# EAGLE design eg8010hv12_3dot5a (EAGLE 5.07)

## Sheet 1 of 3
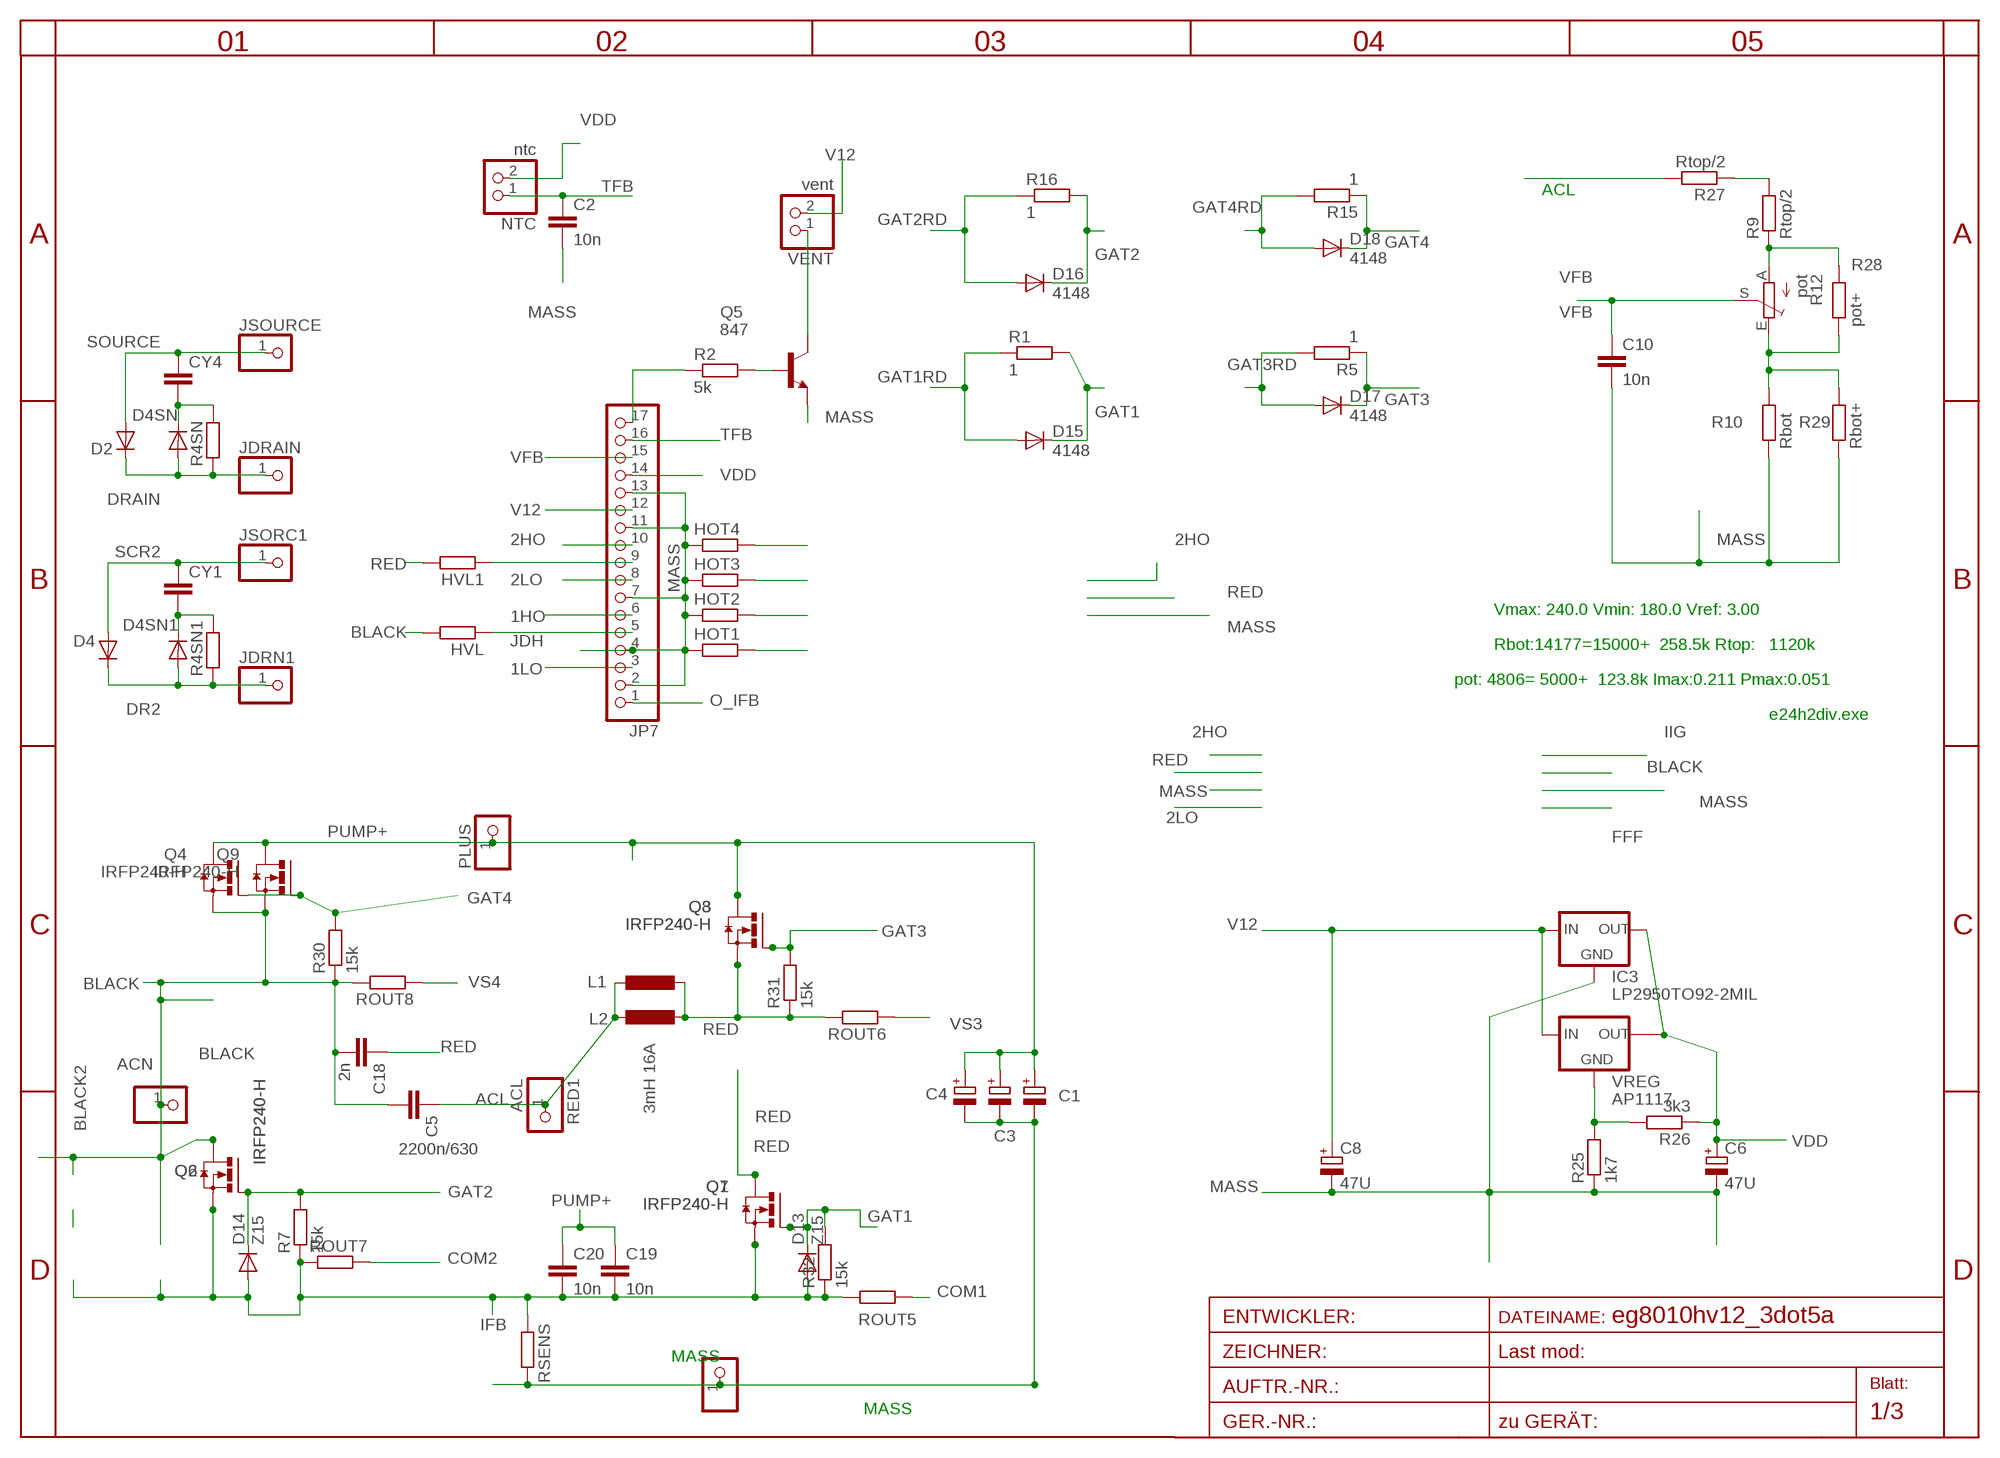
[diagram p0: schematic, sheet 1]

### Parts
BLACK2  ACN  PINHD-1X12MM3  [1X2MM3]
C1  CPOL-EUE5-13  [E5-13]
C2  10n  C-EUC0805  [C0805]
C3  CPOL-EUE5-13  [E5-13]
C4  CPOL-EUE5-13  [E5-13]
C5  2200n/630  C-EU275-173X316  [C275-173X316]
C6  47U  CPOL-EUSMCA  [SMC_A]
C8  47U  CPOL-EUSMCA  [SMC_A]
C10  10n  C-EUC0805  [C0805]
C18  2n  C-EU050-024X044  [C050-024X044]
C19  10n  C-EU050-024X044  [C050-024X044]
C20  10n  C-EU050-024X044  [C050-024X044]
CY1  CXXC10B5  [XC10B5]
CY4  CXXC10B5  [XC10B5]
D2  DIODE-SMC  [SMC]
D4  DIODE-SMC  [SMC]
D4SN  DIODE-P1-10  [P1-10]
D4SN1  DIODE-P1-10  [P1-10]
D13  Z15  DIODE-MINIMELF  [MINIMELF]
D14  Z15  DIODE-MINIMELF  [MINIMELF]
D15  4148  DIODE-MINIMELF  [MINIMELF]
D16  4148  DIODE-MINIMELF  [MINIMELF]
D17  4148  DIODE-MINIMELF  [MINIMELF]
D18  4148  DIODE-MINIMELF  [MINIMELF]
HOT1  R-EU_R0805  [R0805]
HOT2  R-EU_R0805  [R0805]
HOT3  R-EU_R0805  [R0805]
HOT4  R-EU_R0805  [R0805]
HVL  R-EU_R1005  [R1005]
HVL1  R-EU_R1005  [R1005]
IC3  LP2950TO92-2MIL  [TO92-2MIL]
JDRAIN  PINHD-1X11MM0  [1X1MM0]
JDRN1  PINHD-1X11MM0  [1X1MM0]
JP7  PINHD-1X17  [1X17]
JSORC1  PINHD-1X11MM0  [1X1MM0]
JSOURCE  PINHD-1X11MM0  [1X1MM0]
L1  L-EU4.13  [0204/13]
L2  3mH 16A  L-EURNG  [RING]
MINUS  PINHD-1X12MM3  [1X2MM3]
NTC  ntc  PINHD-1X2STR  [1X02]
PLUS  PINHD-1X12MM3  [1X2MM3]
Q1  IRFP240-H  [TO247BH]
Q2  IRFP240-H  [TO247BH]
Q3  IRFP240-H  [TO247BH]
Q4  IRFP240-H  [TO247BH]
Q5  847  BC847SMD  [SOT23]
Q6  IRFP240-H  [TO247BH]
Q7  IRFP240-H  [TO247BH]
Q8  IRFP240-H  [TO247BH]
Q9  IRFP240-H  [TO247BH]
R1  1  R-EU_R2512  [R2512]
R2  5k  R-EU_R0805  [R0805]
R4SN  R-EU_0207/10  [0207/10]
R4SN1  R-EU_0207/10  [0207/10]
R5  1  R-EU_R2512  [R2512]
R7  15k  R-EU_R1206  [R1206]
R9  Rtop/2  R-EU_R1206  [R1206]
R10  Rbot  R-EU_R0805  [R0805]
R12  pot  TRIM_EU-B64Y  [B64Y]
R15  1  R-EU_R2512  [R2512]
R16  1  R-EU_R2512  [R2512]
R25  1k7  R-EU_R0805  [R0805]
R26  3k3  R-EU_R0805  [R0805]
R27  Rtop/2  R-EU_R1206  [R1206]
R28  pot+  R-EU_R0805  [R0805]
R29  Rbot+  R-EU_R0805  [R0805]
R30  15k  R-EU_R1206  [R1206]
R31  15k  R-EU_R1206  [R1206]
R32  15k  R-EU_R1206  [R1206]
RED1  ACL  PINHD-1X12MM3  [1X2MM3]
ROUT5  R-EU_R2512  [R2512]
ROUT6  R-EU_R2512  [R2512]
ROUT7  R-EU_R2512  [R2512]
ROUT8  R-EU_R2512  [R2512]
RSENS  R-EU_WIRE  [WIRE]
VENT  vent  PINHD-1X2STR  [1X02]
VREG  AP1117  [SOT223]

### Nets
1HO: HOT2.2 JP7.6 ; also sheet 3
1LO: HOT1.2 JP7.3 ; also sheet 3
2HO: HOT4.2 JP7.10 ; also sheet 3
2LO: HOT3.2 JP7.8 ; also sheet 3
ACL: C5.1 L1.1 L2.2 R27.2 RED1.1
BLACK: BLACK2.1 C5.2 C18.2 HVL.2 Q2.D Q4.S Q6.D Q9.S R30.1 ROUT8.2
COM1: ROUT5.1 ; also sheet 3
COM2: ROUT7.2 ; also sheet 3
DFG: HVL1.1 JP7.9
DR2: D4.C D4SN1.A JDRN1.1 R4SN1.1
DRAIN: D2.C D4SN.A JDRAIN.1 R4SN.1
GAT1: D13.C D15.C Q1.G Q7.G R1.2 R32.2
GAT1RD: D15.A R1.1 ; also sheet 3
GAT2: D14.C D16.C Q2.G Q6.G R7.2 R16.2
GAT2RD: D16.A R16.1 ; also sheet 3
GAT3: D17.C Q3.G Q8.G R5.1 R31.2
GAT3RD: D17.A R5.2 ; also sheet 3
GAT4: D18.C Q4.G Q9.G R15.1 R30.2
GAT4RD: D18.A R15.2 ; also sheet 3
IFB: C19.2 C20.2 D13.A D14.A Q1.S Q2.S Q6.S Q7.S R7.1 R32.1 ROUT5.2 ROUT7.1 RSENS.1 ; also sheet 2,3
JDH: HVL.1 JP7.5
MASS: C1.- C2.2 C3.- C4.- C6.- C8.- C10.2 HOT1.1 HOT2.1 HOT3.1 HOT4.1 IC3.2(GND) JP7.2 JP7.4 JP7.7 JP7.11 JP7.13 MINUS.1 Q5.2(E) R10.1 R25.1 R29.1 RSENS.2 ; also sheet 2,3
N$1: Q5.3(C) VENT.1
N$2: Q5.1(B) R2.2
N$3: JP7.17 R2.1
N$17: R25.2 R26.2 VREG.1(GND)
N$23: R9.2 R27.1
N$29: R10.2 R12.E R28.1 R29.2
N$30: R9.1 R12.A R28.2
O_IFB: JP7.1 ; also sheet 3
PUMP+: C1.+ C3.+ C4.+ C19.1 C20.1 PLUS.1 Q3.D Q4.D Q8.D Q9.D ; also sheet 2
RED: C18.1 HVL1.2 L1.2 L2.1 Q1.D Q3.S Q7.D Q8.S R31.1 ROUT6.2 ; also sheet 2
SCR2: CY1.1 D4.A JSORC1.1
SNUB1: CY1.2 D4SN1.C R4SN1.2
SNUB2: CY4.2 D4SN.C R4SN.2
SOURCE: CY4.1 D2.A JSOURCE.1
TFB: C2.1 JP7.16 NTC.1 ; also sheet 2
V12: C8.+ IC3.3(IN) JP7.12 VENT.2 VREG.3(IN) ; also sheet 2,3
VDD: C6.+ IC3.1(OUT) JP7.14 NTC.2 R26.1 VREG.4(TAB) ; also sheet 2
VFB: C10.1 JP7.15 R12.S ; also sheet 2
VS3: ROUT6.1 ; also sheet 3
VS4: ROUT8.1 ; also sheet 3
Unconnected: VREG.2(OUT)

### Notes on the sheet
- Vmax: 240.0 Vmin: 180.0 Vref: 3.00
- Rbot:14177=15000+  258.5k Rtop:   1120k
- pot: 4806= 5000+  123.8k Imax:0.211 Pmax:0.051
- e24h2div.exe

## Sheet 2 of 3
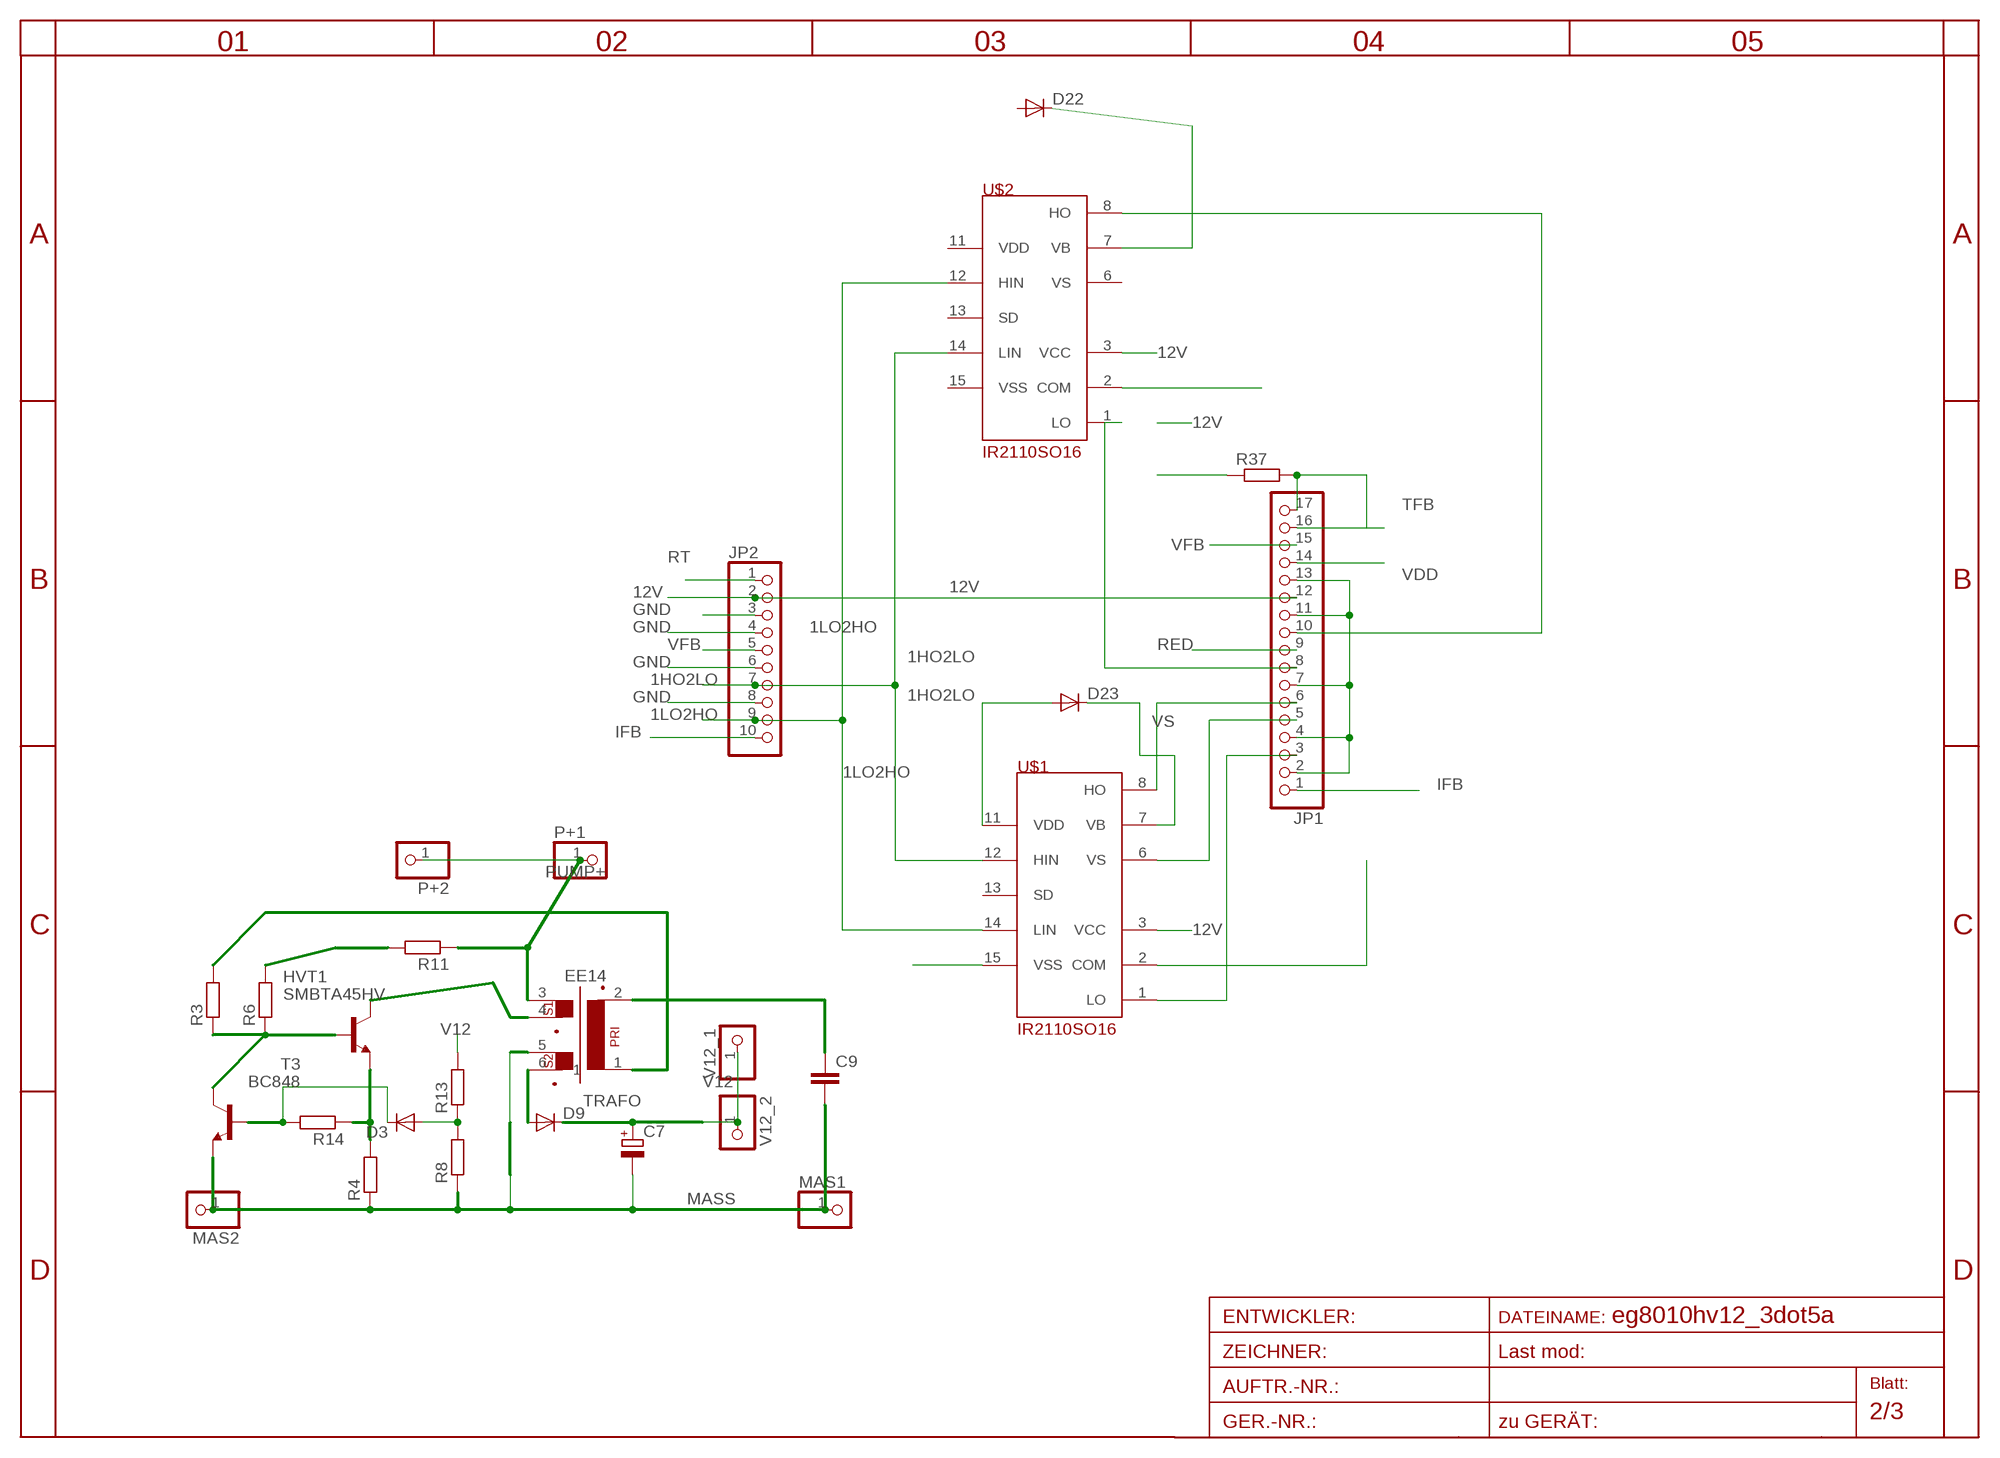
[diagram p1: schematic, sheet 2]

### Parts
C7  CPOL-EUSMCA  [SMC_A]
C9  C-EUC0805  [C0805]
D3  DIODE-MINIMELF  [MINIMELF]
D9  DIODE-SMA-DO214  [SMA-DO214AC]
D22  DIODE-SMA-DO214  [SMA-DO214AC]
D23  DIODE-SMA-DO214  [SMA-DO214AC]
HVT1  SMBTA45HV  [SOT23HV]
JP1  PINHD-1X17  [1X17]
JP2  PINHD-1X100X05  [1X10]
MAS1  PINHD-1X11X0.4  [1X01]
MAS2  PINHD-1X11X0.4  [1X01]
P+1  PINHD-1X11X0.4  [1X01]
P+2  PINHD-1X11X0.4  [1X01]
R3  R-EU_R0805  [R0805]
R4  R-EU_R0805  [R0805]
R6  R-EU_R1206  [R1206]
R8  R-EU_R0805  [R0805]
R11  R-EU_R1206  [R1206]
R13  R-EU_R0805  [R0805]
R14  R-EU_R0805  [R0805]
R37  R-EU_0204/2V  [0204V]
T3  BC848  [SOT23]
TRAFO  EE14  [EE14]
U$1  IR2110SO16  [SO16DW]
U$2  IR2110SO16  [SO16DW]
V12_1  PINHD-1X11X0.4  [1X01]
V12_2  PINHD-1X11X0.4  [1X01]

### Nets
1HO2LO: JP2.7 U$1.12(HIN) U$2.14(LIN)
1LO2HO: JP2.9 U$1.14(LIN) U$2.12(HIN)
12V: D23.A JP1.12 JP2.2 U$1.3(VCC) U$1.11(VDD)
A: D9.A TRAFO.6
B1C2: HVT1.1(B) R3.1 R6.1 T3.C
BT1: D3.C R14.2 T3.B
C1: HVT1.3(C) TRAFO.4
EB: HVT1.2(E) R4.2 R14.1
GND: JP1.2 JP1.4 JP1.7 JP1.11 JP1.13 JP2.3 JP2.4 JP2.6 JP2.8 R37.1
IFB: JP1.1 JP2.10 U$1.2(COM) U$2.2(COM) ; also sheet 1,3
MASS: C7.- C9.2 MAS1.1 MAS2.1 R4.1 R8.1 T3.E TRAFO.5 U$1.15(VSS) ; also sheet 1,3
N$6: R3.2 TRAFO.1
N$7: C9.1 TRAFO.2
N$8: R6.2 R11.2
N$10: D3.A R8.2 R13.1
N$15: JP1.3 U$1.1(LO)
N$19: JP1.6 U$1.8(HO)
N$21: JP1.8 U$2.1(LO)
N$27: JP1.10 U$2.8(HO)
PUMP+: P+1.1 P+2.1 R11.1 TRAFO.3 ; also sheet 1
RED: JP1.9 ; also sheet 1
RT: JP2.1
TFB: JP1.16 JP1.17 R37.2 ; also sheet 1
V12: C7.+ D9.K(C) R13.2 V12_1.1 V12_2.1 ; also sheet 1,3
VB: D22.K(C) D23.K(C) U$1.7(VB) U$2.7(VB)
VDD: JP1.14 ; also sheet 1
VFB: JP1.15 JP2.5 ; also sheet 1
VS: JP1.5 U$1.6(VS)
Unconnected: D22.A U$1.13(SD) U$2.3(VCC) U$2.6(VS) U$2.11(VDD) U$2.13(SD) U$2.15(VSS)

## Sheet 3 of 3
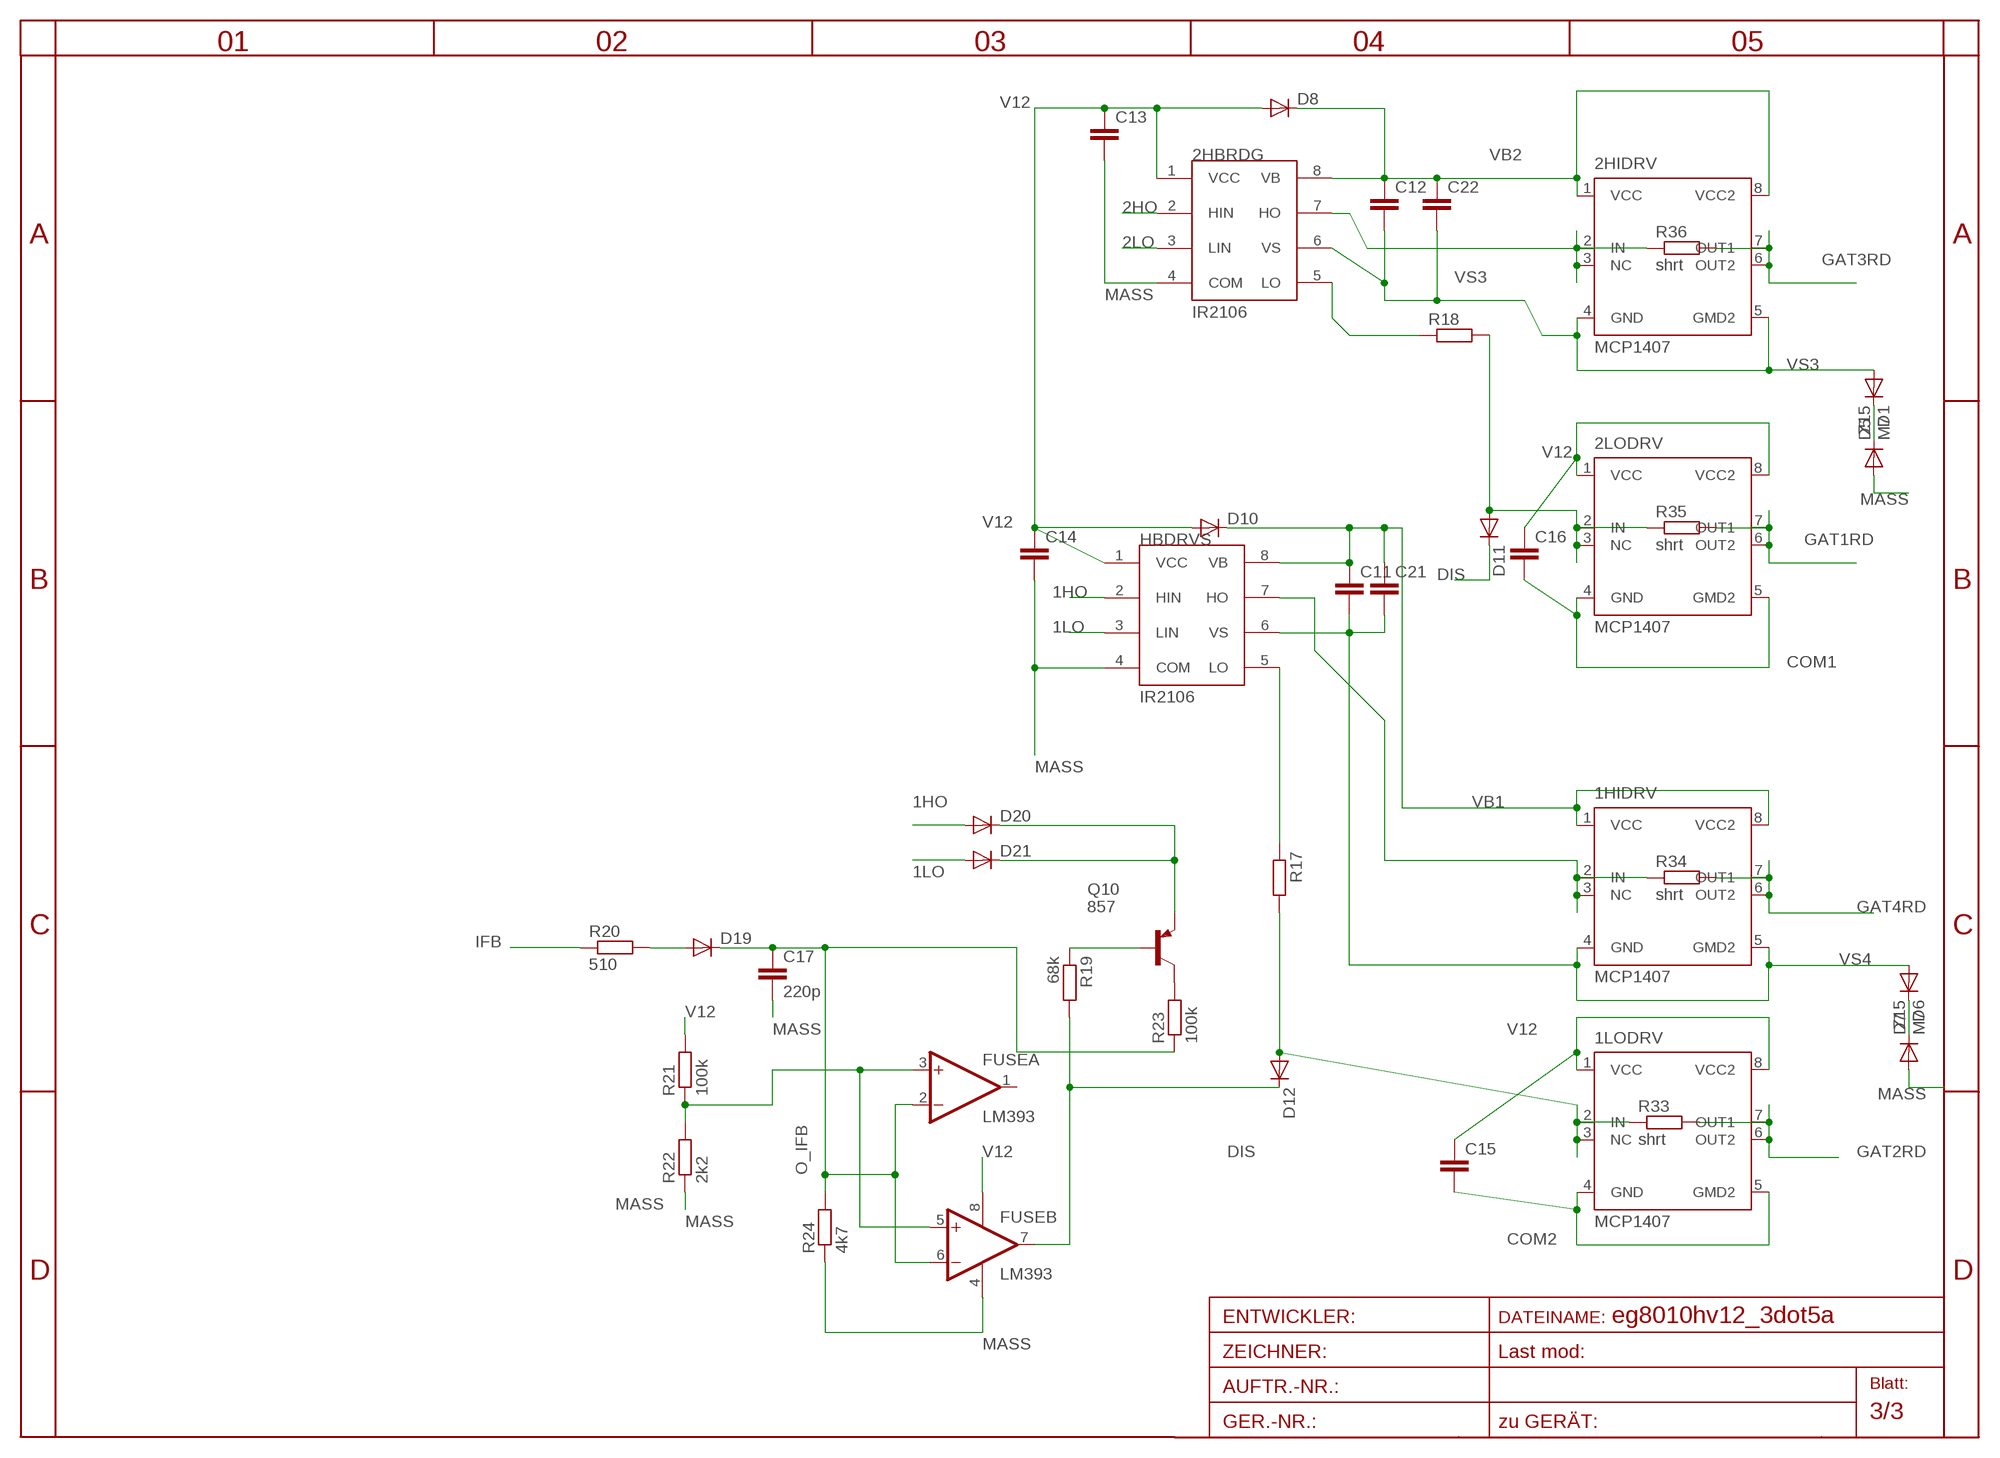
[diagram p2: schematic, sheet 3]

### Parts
1HIDRV  MCP1407  [SO-08M]
1LODRV  MCP1407  [SO-08M]
2HBRDG  IR2106  [SO8-5]
2HIDRV  MCP1407  [SO-08M]
2LODRV  MCP1407  [SO-08M]
C11  C-EUC058MLCC  [C058-020X040]
C12  C-EUC058MLCC  [C058-020X040]
C13  C-EUC1206  [C1206]
C14  C-EUC1206  [C1206]
C15  C-EUC1206  [C1206]
C16  C-EUC1206  [C1206]
C17  220p  C-EUC0805  [C0805]
C21  C-EUC1206  [C1206]
C22  C-EUC1206  [C1206]
D1  Z15  DIODE-MINIMELF  [MINIMELF]
D5  M7  DIODE-SMA-DO214  [SMA-DO214AC]
D6  Z15  DIODE-MINIMELF  [MINIMELF]
D7  M7  DIODE-SMA-DO214  [SMA-DO214AC]
D8  DIODE-SMA-DO214  [SMA-DO214AC]
D10  DIODE-SMA-DO214  [SMA-DO214AC]
D11  DIODE-MINIMELF  [MINIMELF]
D12  DIODE-MINIMELF  [MINIMELF]
D19  DIODE-SOT23  [SOT23]
D20  DIODE-SOT23  [SOT23]
D21  DIODE-SOT23  [SOT23]
FUSE  LM393  LM358D  [SO08]
HBDRVS  IR2106  [SO8-5]
Q10  857  BC857ALT1SMD  [SOT23-BEC]
R17  R-EU_0207-17  [0207/17]
R18  R-EU_0204/5  [0204/5]
R19  68k  R-EU_R0805  [R0805]
R20  510  R-EU_R0805  [R0805]
R21  100k  R-EU_R0805  [R0805]
R22  2k2  R-EU_R0805  [R0805]
R23  100k  R-EU_R0805  [R0805]
R24  4k7  R-EU_R0805  [R0805]
R33  shrt  R-EU_R1206  [R1206]
R34  shrt  R-EU_R1206  [R1206]
R35  shrt  R-EU_R1206  [R1206]
R36  shrt  R-EU_R1206  [R1206]

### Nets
1HO: D20.1(A) HBDRVS.2(HIN) ; also sheet 1
1LO: D21.1(A) HBDRVS.3(LIN) ; also sheet 1
2HO: 2HBRDG.2(HIN) ; also sheet 1
2LO: 2HBRDG.3(LIN) ; also sheet 1
COM1: 2LODRV.4(GND) 2LODRV.5(GMD2) C16.2 ; also sheet 1
COM2: 1LODRV.4(GND) 1LODRV.5(GMD2) C15.2 ; also sheet 1
DIS: D11.C D12.C FUSE.7(B:OUT) R19.2
GAT1RD: 2LODRV.6(OUT2) 2LODRV.7(OUT1) R35.2 ; also sheet 1
GAT2RD: 1LODRV.6(OUT2) 1LODRV.7(OUT1) R33.2 ; also sheet 1
GAT3RD: 2HIDRV.6(OUT2) 2HIDRV.7(OUT1) R36.2 ; also sheet 1
GAT4RD: 1HIDRV.6(OUT2) 1HIDRV.7(OUT1) R34.2 ; also sheet 1
IFB: R20.1 ; also sheet 1,2
MASS: 2HBRDG.4(COM) C13.2 C14.2 C17.2 D5.A D7.A FUSE.4(P:V-) HBDRVS.4(COM) R22.1 R24.1 ; also sheet 1,2
N$4: 2HBRDG.5(LO) R18.1
N$5: 1LODRV.2(IN) 1LODRV.3(NC) D12.A R17.2 R33.1
N$9: FUSE.3(A:+IN) FUSE.5(B:+IN) R21.1 R22.2
N$11: HBDRVS.5(LO) R17.1
N$12: 2HBRDG.7(HO) 2HIDRV.2(IN) 2HIDRV.3(NC) R36.1
N$13: 1HIDRV.2(IN) 1HIDRV.3(NC) HBDRVS.7(HO) R34.1
N$14: D19.1(A) R20.2
N$16: 2LODRV.2(IN) 2LODRV.3(NC) D11.A R18.2 R35.1
N$18: D20.3(C) D21.3(C) Q10.E
N$20: D1.C D5.K(C)
N$24: D6.C D7.K(C)
N$25: Q10.B R19.1
N$26: Q10.C R23.2
O_IFB: C17.1 D19.3(C) FUSE.2(A:-IN) FUSE.6(B:-IN) R23.1 R24.2 ; also sheet 1
V12: 1LODRV.1(VCC) 1LODRV.8(VCC2) 2HBRDG.1(VCC) 2LODRV.1(VCC) 2LODRV.8(VCC2) C13.1 C14.1 C15.1 C16.1 D8.A D10.A FUSE.8(P:V+) HBDRVS.1(VCC) R21.2 ; also sheet 1,2
VB1: 1HIDRV.1(VCC) 1HIDRV.8(VCC2) C11.1 C21.1 D10.K(C) HBDRVS.8(VB)
VB2: 2HBRDG.8(VB) 2HIDRV.1(VCC) 2HIDRV.8(VCC2) C12.1 C22.1 D8.K(C)
VS3: 2HBRDG.6(VS) 2HIDRV.4(GND) 2HIDRV.5(GMD2) C12.2 C22.2 D1.A ; also sheet 1
VS4: 1HIDRV.4(GND) 1HIDRV.5(GMD2) C11.2 C21.2 D6.A HBDRVS.6(VS) ; also sheet 1
Unconnected: FUSE.1(A:OUT)

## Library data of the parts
1HIDRV 1LODRV 2HIDRV 2LODRV = microchip:MCP1407
2HBRDG HBDRVS = irf-2:IR2106
BLACK2 JDRAIN JDRN1 JSORC1 JSOURCE MAS1 MAS2 MINUS P+1 P+2 PLUS RED1 V12_1 V12_2 = pinhead:PINHD-1X1: PIN HEADER
C1 C3 C4 C6-C8 = rcl:CPOL-EU: POLARIZED CAPACITOR, European symbol
C2 C5 C9-C22 = rcl:C-EU: CAPACITOR, European symbol
CY1 CY4 = rcl:CX: X CAPACITOR
D1-D4 D4SN D4SN1 D5-D23 = diode:DIODE-: DIODE
FUSE = linear:LM358: OP AMP also LM158; LM258; LM2904 Source: http://cache.national.com/ds/LM/LM158.pdf
HOT1-HOT4 HVL HVL1 R1-R4 R4SN R4SN1 R5-R8 R11 R13-R24 R30-R37 ROUT5-ROUT8 RSENS = rcl:R-EU_: RESISTOR, European symbol
HVT1 = transistor-npn:SMBTA45
IC3 = v-reg:LP2950?*: Source: http://cache.national.com/ds/LP/LP2950.pdf
JP1 JP7 = pinhead:PINHD-1X17: PIN HEADER
JP2 = pinhead:PINHD-1X10: PIN HEADER
L1 L2 = rcl:L-EU: INDUCTOR, European symbol
NTC VENT = pinhead:PINHD-1X2: PIN HEADER
Q1-Q4 Q6-Q9 = transistor-power:IRFP240: HEXFET Power MosFet Source: http://www.irf.com/
Q5 = transistor-npn:BC847*: NPN Transistor
Q10 = transistor-pnp:BC857*: PNP Transistror
R9 R10 R25-R29 = rcl-2:R-EU_: RESISTOR, European symbol
R12 = pot:TRIM_EU-: POTENTIOMETER
T3 = transistor:BC848: NPN TRANSISTOR
TRAFO = trafo:EE14
U$1 U$2 = ir2112:IR2110
VREG = v-reg:AP1117

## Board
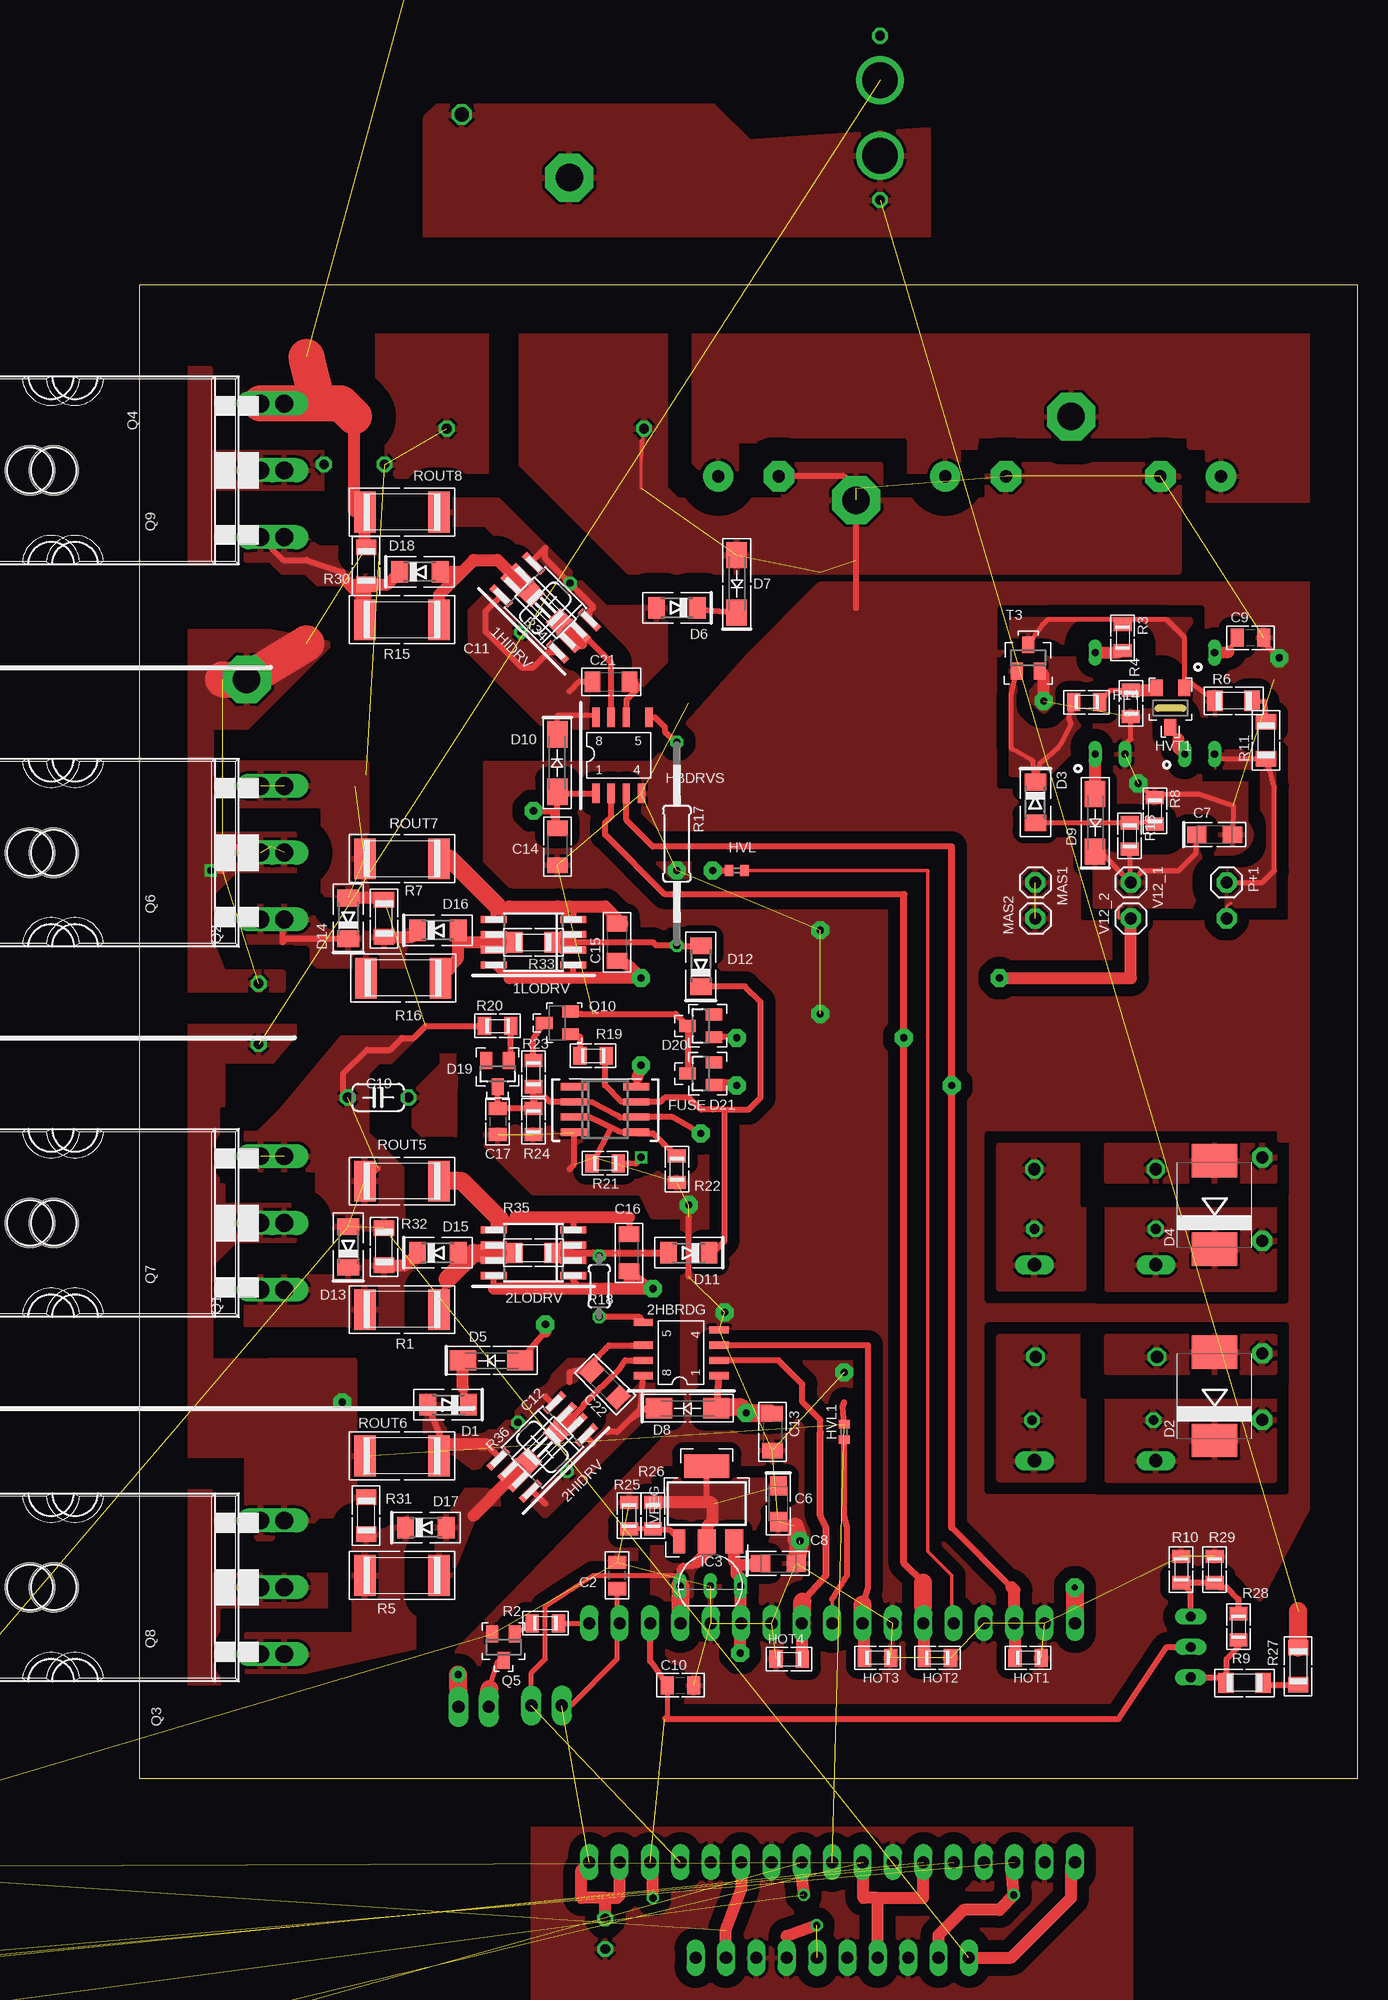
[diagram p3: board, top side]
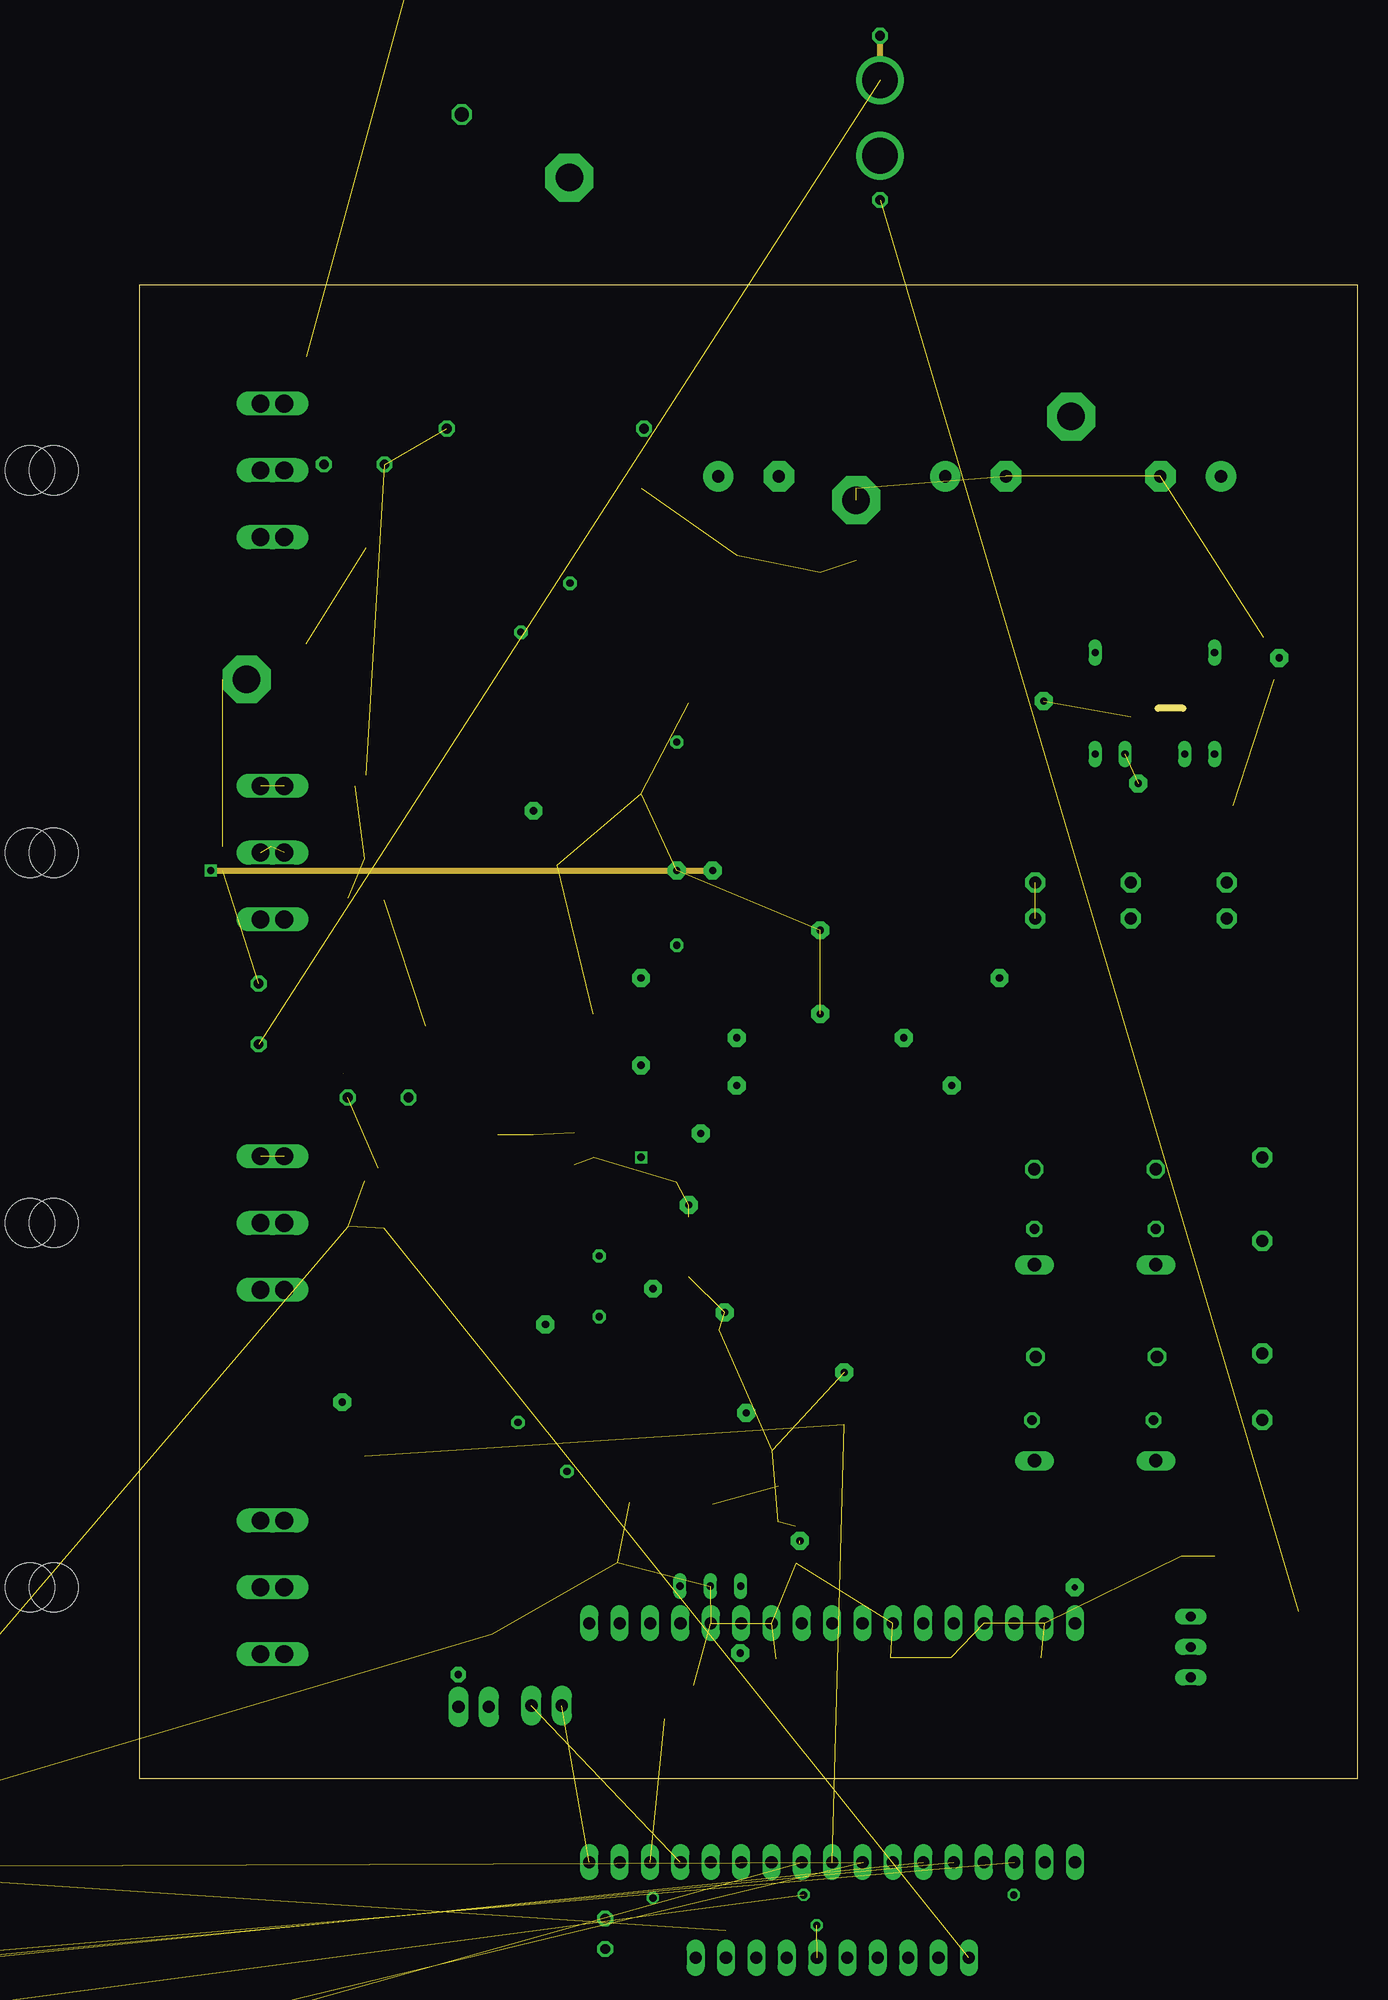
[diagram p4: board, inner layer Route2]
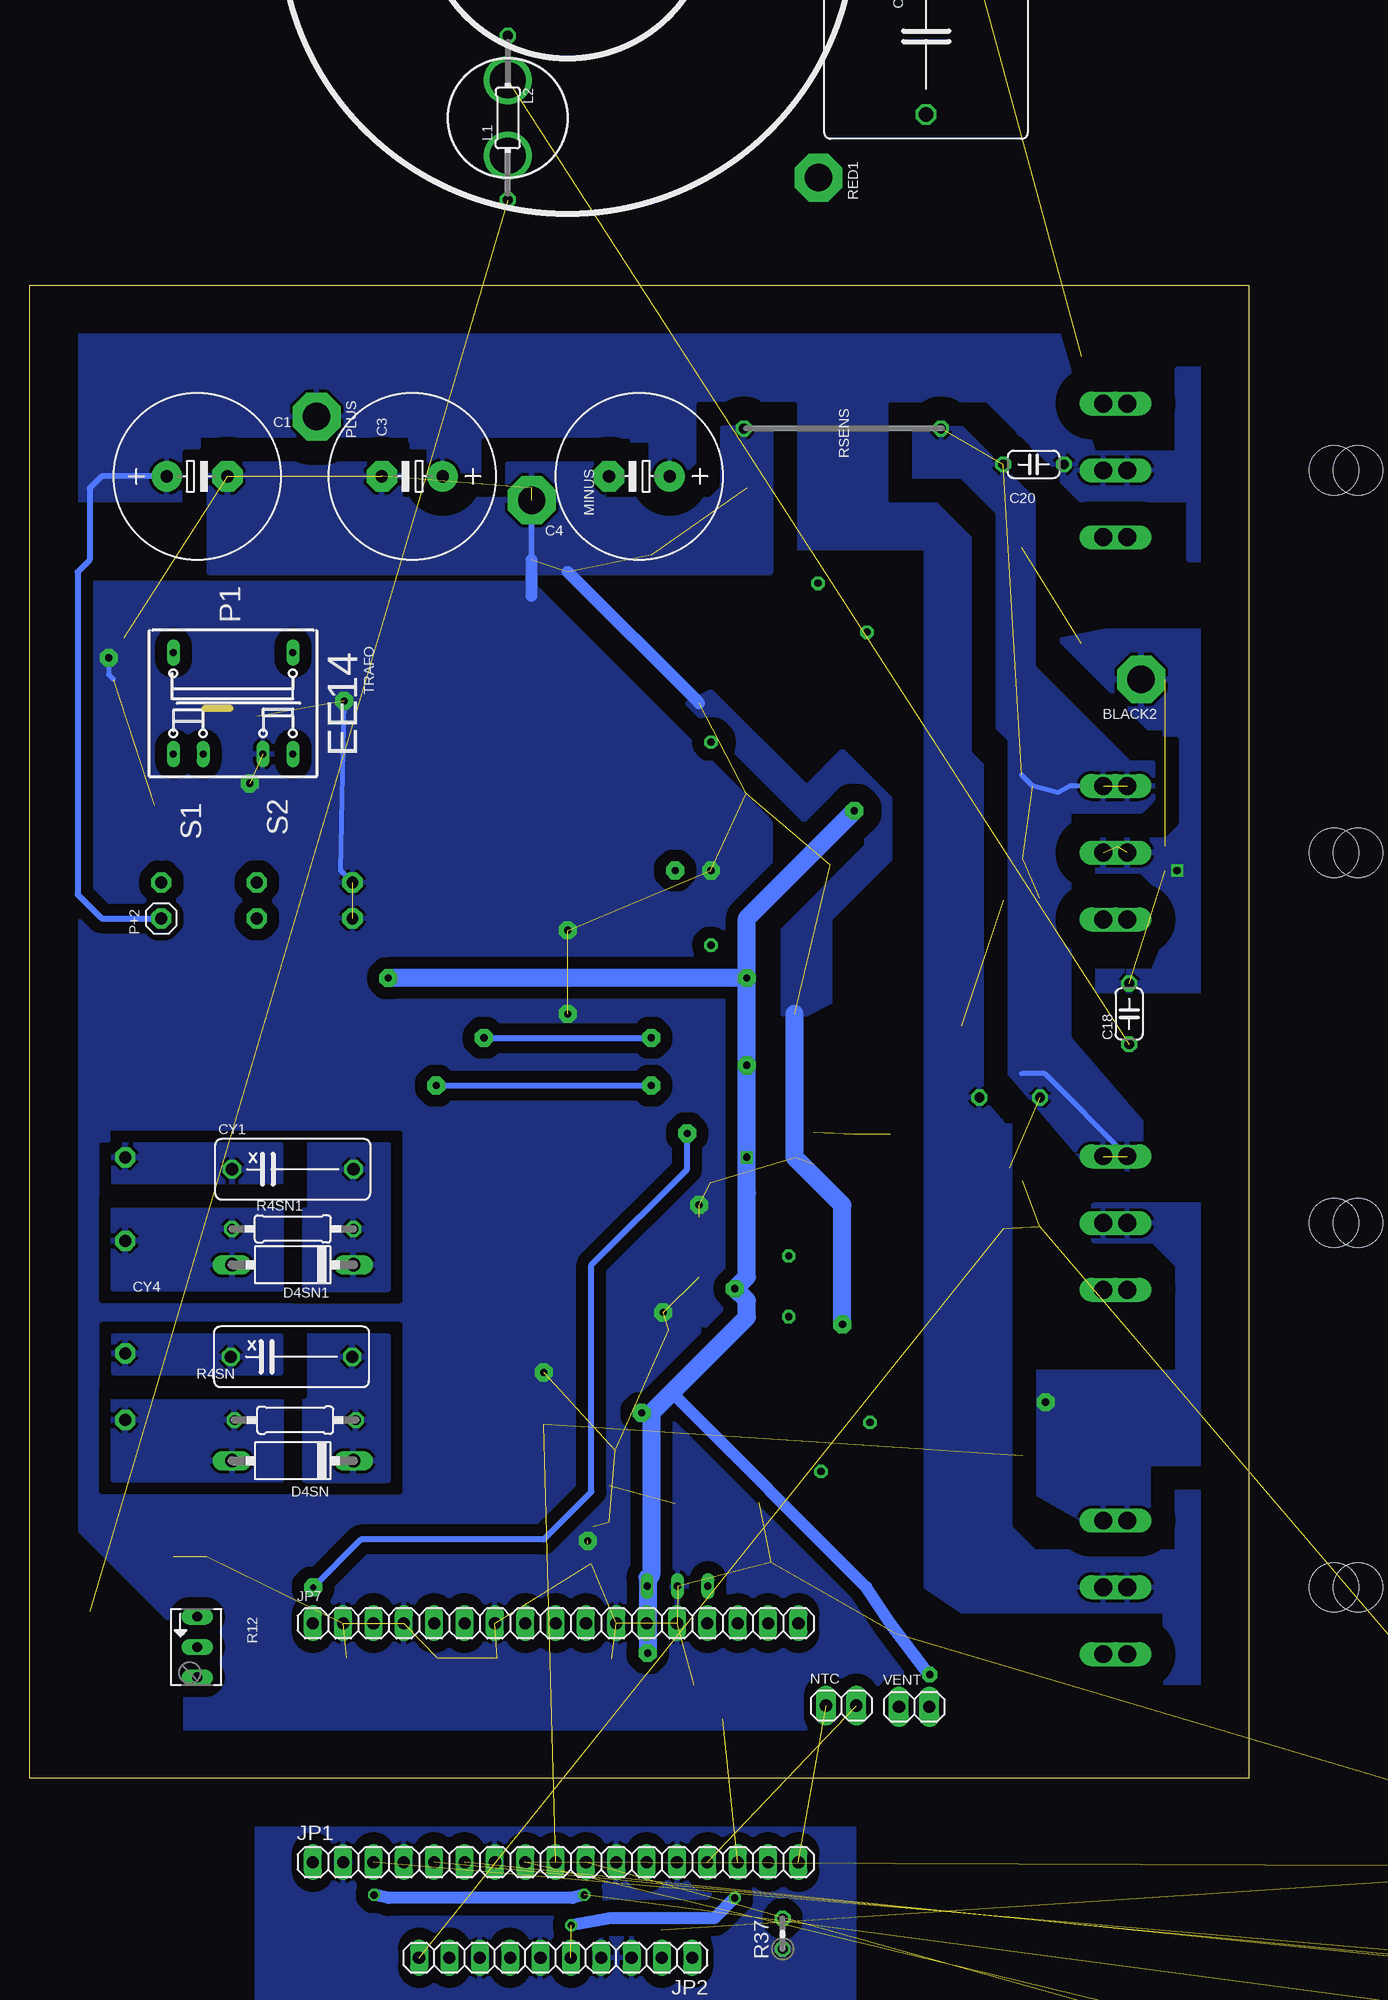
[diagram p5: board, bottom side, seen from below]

Size 102 x 125 mm. Coordinates in mm from the lower left corner, seen from the top.
Outline: 0,0 102,0 102,125 0,125 0,0
Copper layers (1*16): Top 0.035mm / dielectric 1.5mm / Bottom 0.035mm
Design rules "default *": minimum track width 10mil, minimum drill 20mil, track to track 8mil, track to pad 8mil, pad to pad 8mil, via to via 8mil, smd to smd 8mil, copper to edge 4mm, drill to drill 8mil, minimum pad ring 10mil, minimum via ring 8mil, stop-mask expansion 4mil, vias tented up to drill 0mil, thermal gap 10mil

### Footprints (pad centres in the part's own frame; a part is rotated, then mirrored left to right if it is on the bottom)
SO-08M = smd 0.6 x 2.2: 1 -1.905,-3.33; 2 -0.635,-3.33; 3 0.635,-3.33; 4 1.905,-3.33; 5 1.905,3.33; 6 0.635,3.33; 7 -0.635,3.33; 8 -1.905,3.33
SO8-5 = smd 0.61 x 1.626: 1 -1.27,-2.54; 2 0,-2.54; 3 1.27,-2.54; 4 2.54,-2.54; 5 3.175,3.81; 6 1.27,3.81; 7 0,3.81; 8 -1.27,3.81
1X2MM3 = drill 2.3 pad 4 octagon: 1 0,0
E5-13 = drill 1.016 pad 2.54 round: + -2.54,0 | drill 1.016 pad 2.54 octagon: - 2.54,0
C0805 = smd 1.1 x 1.5: 1 -1.1,0; 2 1.1,0
C275-173X316 = drill 1.194 octagon: 1 -13.716,0; 2 13.716,0
SMC_A = smd 1.6 x 1.4: + -1.5,0; - 1.5,0
C058-020X040 = drill 0.6 octagon: 1 -2.9,0; 2 2.9,0
C1206 = smd 1.3 x 1.7: 1 -1.55,0; 2 1.55,0
C050-024X044 = drill 0.813 octagon: 1 -2.54,0; 2 2.54,0
XC10B5 = drill 1.016 octagon: 1 -5.08,0; 2 5.08,0
MINIMELF = smd 1.4 x 1.8: A 1.7,0; C -1.7,0
SMC = smd 2.8 x 3.8: A 3.7,0; C -3.7,0
P1-10 = drill 1.118 long: A 5.08,0; C -5.08,0
SMA-DO214AC = smd 2.2 x 1.7: A 2.4,0; K -2.4,0
SOT23 = smd 1 x 1.4: 1 -0.95,-1.1; 2 0.95,-1.1; 3 0,1.1
SO08 = smd 0.6 x 2.2: 1 -1.905,-2.6; 2 -0.635,-2.6; 3 0.635,-2.6; 4 1.905,-2.6; 5 1.905,2.6; 6 0.635,2.6; 7 -0.635,2.6; 8 -1.905,2.6
R0805 = smd 1.1 x 1.5: 1 -1.1,0; 2 1.1,0
R1005 = smd 0.7 x 0.9: 1 -0.65,0; 2 0.65,0
SOT23HV = smd 1 x 1.4: 1 -1.15,-1.7; 2 1.15,-1.7; 3 0,1.6
TO92-2MIL = drill 0.6 pad 0.813 long: 1 -2.54,0; 2 0,0; 3 2.54,0
1X1MM0 = drill 1 pad 1.676 octagon: 1 0,0
1X17 = drill 1.016 long: 1 -20.32,0; 2 -17.78,0; 3 -15.24,0; 4 -12.7,0; 5 -10.16,0; 6 -7.62,0; 7 -5.08,0; 8 -2.54,0; 9 0,0; 10 2.54,0; 11 5.08,0; 12 7.62,0; 13 10.16,0; 14 12.7,0; 15 15.24,0; 16 17.78,0; 17 20.32,0
1X10 = drill 1.016 long: 1 -11.43,0; 2 -8.89,0; 3 -6.35,0; 4 -3.81,0; 5 -1.27,0; 6 1.27,0; 7 3.81,0; 8 6.35,0; 9 8.89,0; 10 11.43,0
0204/13 = drill 0.813 octagon: 1 -6.872,0; 2 6.872,0
RING = drill 3 pad 4 round: 1 -3.15,0; 2 3.15,0
1X01 = drill 1 pad 1.676 octagon: 1 0,0
1X02 = drill 1.016 pad 1.676 long: 1 -1.27,0; 2 1.27,0
TO247BH = drill 1.499 long: D 0,-10.16; G -5.588,-10.16; S 5.588,-10.16 | hole 4.115: 0,9.144
SOT23-BEC = smd 1 x 1.4: B -0.95,-1.1; C 0,1.1; E 0.95,-1.1
R2512 = smd 1.8 x 3.4: 1 -3.1,0; 2 3.1,0
0207/10 = drill 0.813 octagon: 1 -5.08,0; 2 5.08,0
R1206 = smd 1.3 x 1.7: 1 -1.55,0; 2 1.55,0
B64Y = drill 0.813 long: A 2.54,0; E -2.54,0; S 0,0
0207/17 = drill 0.6 octagon: 1 -8.5,0; 2 8.5,0
0204/5 = drill 0.6 octagon: 1 -2.54,0; 2 2.54,0
0204V = drill 0.813 octagon: 1 -1.27,0; 2 1.27,0
WIRE = drill 0.813 octagon: 1 -8.25,0; 2 8.25,0
SOT23' = smd 1 x 1.4: B -0.95,-1.1; C 0,1.1; E 0.95,-1.1
EE14 = drill 0.6 pad 1 long: 1 4.25,-5; 2 4.25,5; 3 -4.25,5 | drill 0.6 pad 1.016 long: 4 -4.25,2.5; 5 -4.25,-2.5; 6 -4.25,-5
SO16DW = smd 0.6 x 2.2: 1 -4.445,-4.6; 2 -3.175,-4.6; 3 -1.905,-4.6; 4 -0.635,-4.6; 5 0.635,-4.6; 6 1.905,-4.6; 7 3.175,-4.6; 8 4.445,-4.6; 9 4.445,4.6; 10 3.175,4.6; 11 1.905,4.6; 12 0.635,4.6; 13 -0.635,4.6; 14 -1.905,4.6; 15 -3.175,4.6; 16 -4.445,4.6
SOT223 = smd 1 x 2: 1 -2.3,-3.15 | smd 1.5 x 2: 2 0,-3.15; 3 2.3,-3.15 | smd 3.8 x 2: 4 0,3.15

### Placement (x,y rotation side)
1HIDRV  34,98 45 top
1LODRV  33,70 90 top
2HBRDG  46,35 90 top
2HIDRV  33.75,27.75 135 top
2LODRV  33,44 90 top
BLACK2  9,92 180 bottom
C1  88,109 0 bottom
C2  40,17 90 top
C3  70,109 180 bottom
C4  51,109 180 bottom
C5  not placed on the board
C6  53.5,23 270 top
C7  90,79 0 top
C8  53.5,18 0 top
C9  93,95.5 0 top
C10  45.3,7.8 0 top
C11  34,98 45 top
C12  33.75,27.75 135 top
C13  53,29 270 top
C14  35,78 270 top
C15  40,70 90 top
C16  41,44 90 top
C17  30,55 270 top
C18  10,64 90 bottom
C19  20,57 180 top
C20  18,110 180 bottom
C21  39.5,91.8 0 top
C22  39,33 135 top
CY1  80,51 0 bottom
CY4  80.1,35.3 0 bottom
D1  25.86,31.28 180 top
D2  90,32 90 top
D3  75,81.7 270 top
D4  90,48 90 top
D4SN  80,26.6 180 bottom
D4SN1  80,43 180 bottom
D5  29.5,35 0 top
D6  45,98 180 top
D7  50,100 90 top
D8  45.9,31 0 top
D9  80,80 90 top
D10  35,85 270 top
D11  46,44 180 top
D12  47,68 90 top
D13  17.5,44.5 90 top
D14  17.5,72 90 top
D15  25,44 0 top
D16  25,71 0 top
D17  24,21 0 top
D18  23.5,101 0 top
D19  30,59 180 top
D20  47,63 90 top
D21  47,59 90 top
D22  not placed on the board
D23  not placed on the board
FUSE  39,56 270 top
HBDRVS  39.5,85 0 top
HOT1  74.4,10.1 180 top
HOT2  66.8,10.1 180 top
HOT3  61.8,10.1 180 top
HOT4  54.4,10 0 top
HVL  50,76 180 top
HVL1  59,29 90 top
HVT1  86.3,89.6 180 top
IC3  47.8,16.1 0 top
JDRAIN  94,30 270 top
JDRN1  94,45 0 top
JP1  58,-7 0 bottom  (outside the outline)
JP2  58,-15 180 bottom  (outside the outline)
JP7  58,13 0 bottom
JSORC1  94,52 0 top
JSOURCE  94,35.6 270 top
L1  62,139 90 bottom  (outside the outline)
L2  62,139 270 bottom  (outside the outline)
MAS1  75,75 270 top
MAS2  75,72 90 top
MINUS  60,107 270 bottom
NTC  34.1,6.1 0 bottom
P+1  91,75 270 top
P+2  91,72 90 bottom
PLUS  78,114 270 bottom
Q1  0,46.5 90 top
Q2  0,77.5 90 top
Q3  0,16 90 top
Q4  0,109.5 90 top
Q5  30.5,11 180 top
Q6  2,77.5 90 top
Q7  2,46.5 90 top
Q8  2,16 90 top
Q9  2,109.5 90 top
Q10  35,63.25 90 top
R1  22,39.25 180 top
R2  34,13 180 top
R3  82.3,95.5 270 top
R4  83,90 90 top
R4SN  79.8,30 0 bottom
R4SN1  80,46 0 bottom
R5  22,17 0 top
R6  91.6,90.2 0 top
R7  20.5,72 270 top
R8  85,81 270 top
R9  92.5,8 0 top
R10  87.2,17.5 270 top
R11  94.3,86.9 90 top
R12  88,11 270 bottom
R13  82.9,78.9 270 top
R14  79.3,90.1 180 top
R15  22,97 0 top
R16  22.1,67 180 top
R17  45,78.25 270 top
R18  38.5,41.2 90 top
R19  38,60.5 0 top
R20  30,63 0 top
R21  39,51.5 0 top
R22  45,51 90 top
R23  33,59 90 top
R24  33,55 90 top
R25  41,22 270 top
R26  43,22 270 top
R27  97,9.4 90 top
R28  92,12.7 270 top
R29  90,17.5 270 top
R30  19,101.5 270 top
R31  19,22 270 top
R32  20.5,44.5 270 top
R33  33,70 180 top
R34  34,98 135 top
R35  33,44 180 top
R36  33.75,27.75 225 top
R37  39,-13 90 bottom  (outside the outline)
RED1  not placed on the board
ROUT5  22,50 180 top
ROUT6  22,27 180 top
ROUT7  22,77 0 top
ROUT8  22,106 180 top
RSENS  34,113 180 bottom
T3  BC848  [SOT23']  74.4,93.8 0 top
TRAFO  85,90 90 bottom
U$1  not placed on the board
U$2  not placed on the board
V12_1  83,75 270 top
V12_2  83,72 90 top
VENT  28,6 0 bottom
VREG  47.5,23 0 top

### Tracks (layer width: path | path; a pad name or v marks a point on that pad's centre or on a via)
1HO  (via drill 0.6 pad 1.5)
  Top 0.5: 64,74 44,74 39,79 39,80 39.5,80.5 HBDRVS.2 | D20.1 49.95,62.05 v50,62
  Top 0.6: 65.6,16.4 64,18 v64,62 64,74
  Top 1: 65.6,14.4 JP7.6 65.7,12.92 HOT2.2
  Top 1.5: 65.6,14.4 65.6,16.4
  Bottom 0.5: v64,62 v50,62
1HO2LO  (2 unrouted)
  Top 1: 65.6,-7 65.6,-10 61.81,-10 | JP2.7 61.81,-10 | 60.6,-7 60.6,-10 61.81,-10
1LO  (via drill 0.6 pad 1.5)
  Top 0.5: 68,78 43,78 40.77,80.23 HBDRVS.3 | 73,16 68,21
  Top 0.6: 68,21 v68,58 68,78
  Top 1: 73,16 73.24,15.76 JP7.3 73.3,12.94 HOT1.2 | D21.1 49,58.05 v50,58
  Bottom 0.5: v68,58 v50,58
1LO2HO  (via drill 0.6, 0.6 pad 1)  (2 unrouted)
  Top 1: JP2.9 66.89,-13.11 69,-11 72,-11 v73.2,-9.75 73,-7.24 | 55.46,-8.46 v55.6,-9.75
  Bottom 1: v55.6,-9.75 56.6,-10 72,-10 v73.2,-9.75
2HO
  Top 0.5: 2HBRDG.2 53.5,35 55.5,33 55.5,31.5 57,30 57,29
  Top 0.6: 55.5,14.8 57.5,17 57.5,21 57,22 57,29
  Top 1: HOT4.2 55.5,12.96 JP7.10
  Top 1.5: JP7.10 55.5,14.8
2LO
  Top 0.5: 60.54,14.54 61,16 61,36.27 2HBRDG.3
  Top 1: HOT3.2 60.7,12.84 JP7.8
  Top 1.5: JP7.8 60.54,14.54
12V  (3 unrouted)
  Top 1: JP1.12 50.41,-9.2 49.1,-12.7 JP2.2
A
  Top 1: D9.A TRAFO.6
ACL  (1 unrouted)
  Top 1.5: R27.2 97,14
  pour Top: 66,138 66,129 24,129 24,139 25,140 48,140 51,137
B1C2
  Top 0.406: R6.1 88.05,91.7 HVT1.1 87.45,95.55 86,97 82.9,97 | 82.7,97 R3.1 82.9,97 | T3.C 75.6,96.6 76,97 82.7,97 | 82.9,97 82.7,97
  pour Top (isolate 2): 88,92 88,97 73,97 73,94 86,94 86,92 89,89 91,89 91,91
BLACK  (via drill 0.6, 0.6 pad 1.5)  (6 unrouted)
  Top 0.5: v48,76 HVL.2 | v6,76 7,76 7,78 11,78
  Top 1: 18,114 18,106.1 ROUT8.2 18.9,103.15 R30.1
  Top 3: 15,115.09 16.91,115.09 18,114 | 15,115.09 Q9.S Q4.S | 14,95 BLACK2.1 7,92 | 15,115.09 14,119
  Route2 0.5: v6,76 v48,76
  pour Top (isolate 2): 16,95 9,88 6,88 6,79 13,79 13,76 8,76 6,74 6,70 7,67.5 12,67.5 12,66 3,66 3,96 11,96
  pour Bottom (isolate 2, rank 5): 17,95 10,88 7,88 7,79 14,79 14,76 9,76 7,74 7,70 8,67.5 13,67.5 13,66 4,66 4,96 12,96
BT1
  Top 0.406: T3.B 73,90.75 73,86.2 74.8,85.2 D3.C 75.4,85 76.9,86.3 77.2,86.7 78,88.3 77.8,88.8 R14.2
  pour Top (isolate 1.5, rank 2): 80,90 80,88 76,84 73,84 73,93 75,93 75,92 77,90
C1
  Top 0.406: HVT1.3 86.3,87.7 87,87
  Top 1: 87,87 87,86.25 TRAFO.4
COM1
  Top 0.5: 31.5,47 31.25,46.75 30.25,46.75 | 2LODRV.4 36.33,46.67 36,47 | 2LODRV.5 29.67,46.67 30,47 | 41,47 C16.2
  Top 1: 41,47 36,47 31.5,47
  Top 1.5: ROUT5.1 27,50 30,47 30.25,46.75
COM2
  Top 0.5: 31,73 30.4,72.4 30.4,72.6 30,73 29.67,72.67 1LODRV.5 | 35,73 36,72 35.69,72 | 40.45,71.55 C15.2 | 26,77 25.81,77.19 ROUT7.2 | 1LODRV.4 36.33,72.67 36,73
  Top 1: 31,73 35,73 36,73 39,73 40.45,71.55
  Top 1.5: 30,73 26,77
DFG
  Top 0.3: JP7.9 58,15
  Top 0.5: HVL1.1 59,22 59.25,21 59.25,17 58,15
DIS
  Top 0.5: R19.2 39,59.9 39,58 40.36,56.63 FUSE.7 43.64,56.63 44,57 46,57 47,56 48,56 49,56 | 49,56 49,45 48,44 D11.C | D12.C 50.7,66.3 52,65 52,57 51,56 49,56
DR2
  pour Top (isolate 2, rank 2): 95,48 81,48 81,41 95,41
  pour Bottom (isolate 2, rank 2): 95,48 81,48 81,41 95,41
DRAIN
  pour Top (isolate 2, rank 2): 95,32 81,32 81,25 95,25
  pour Bottom (isolate 2, rank 2): 95,32 81,32 81,25 95,25
EB
  Top 0.406: R14.1 81.3,91.1 R4.2 | 84.95,91.1 HVT1.2
  Top 1: R4.2 84.95,91.1
GAT1
  Top 1: R32.2 22.25,42.95 D15.C
  pour Top (isolate 2): 9,42 17,42 17,44 24,44 22,38 9,38
GAT1RD
  Top 0.5: R1.1 25.81,41.81 | 2LODRV.6 29.67,44.09 29.77,44 29.77,43.46 2LODRV.7
  Top 1: 28,44 D15.A | 29.77,44 R35.2
  Top 1.5: 29.77,44 28,44 25.81,41.81
GAT2
  Top 0.5: D14.C 12.3,70.3 12,70 12,72 12.07,72 Q6.G
  Top 1: R7.2 22.85,70.45 D16.C
  pour Top (isolate 2, rank 2): 8,73 14,73 21,71 24,71 24,68 15,68 13,70 8,70
GAT2RD
  Top 0.5: R33.2 30.31,70 1LODRV.7 | 1LODRV.6 29.67,70.33 30,70
  Top 1: 26.7,70 26.7,68.7 26,68 26,67.8 R16.1 | 26.7,70 D16.A | 26.7,70 30,70 R33.2
GAT3
  pour Top (isolate 2, rank 3): 9,12 9,9 14,9 23,11 23,22 18,20 18,12
GAT3RD
  Top 0.5: 30.95,24.95 2HIDRV.6 | 2HIDRV.7 31.05,24.95 31,25
  Top 1: 28,22 30.95,24.95 31,25 R36.2
  pour Top (isolate 1.5, rank 2): 28,25 35,28 32,23 29,23 28,22 26,17 25,17 25,22 26,22
GAT4
  Top 0.5: Q4.G 12.07,102 14,102 17,101 17.39,100.18
  Top 1: 17.62,99.95 R30.2 20.75,99.95 D18.C | 17.39,100.18 17.62,99.95 | R15.1 18.9,98.9 19,99 18.57,99 17.62,99.95
  pour Top (isolate 1.5): 8.9,104.5 12.9,104.5 15,103 18,103 19,102 19,101 18,100 15,100 14,101 12,101 11,102 9,102
GAT4RD
  Top 0.5: 1HIDRV.7 31.64,100.36 1HIDRV.6
  Top 1: 27,101 28,102 30,102 31.64,100.36 R34.2 | 27,101 D18.A | R15.2 25.1,99.1 27,101 | R34.2
GND
  pour Top (isolate 1): 33,-1 83,-1 83,-19 33,-19
  pour Bottom (isolate 1): 33,-1 83,-1 83,-19 33,-19
IFB  (14 unrouted)
  Top 0.5: ROUT5.2 20,51.1 | R20.1 24,63 23,62 22,62 21,61 19.07,61 17.07,59 17.07,57.39 C19.2
  Top 1: D14.A 20.35,73.7 R7.1 | JP2.10 73,-15 78,-10 78,-7.32 JP1.1
  Bottom 0.406: Q1.S 17.07,59 19,59 | 19,84 18.08,83.08 16,82.55 14.99,83.09 Q2.S
  pour Bottom (isolate 2): 28,113 28,109 24,109 21,106 21,88 20,87 20,59 14,52 10,51 9,52 9,55 15,62 15,81 9,81 8,82 8,85 10,85 18,93 18,107 24,113
  pour Top (isolate 2, rank 2): 20,121 29,121 29,109 20,109
  pour Top (isolate 2, rank 2): 9,51 9,54 10,54 12,56 17,62 23,62 21,60 20,60 19,59 19,54 22,51 22,46 15,46 15,51
  pour Top (isolate 2, rank 2): 8,85 19,85 19,74 14,74 14,81 8,81
JDH
  Top 0.3: HVL.1 66,76 66,19 68,17 68,13.16 JP7.5
MASS  (via drill 0.6 pad 1.5)  (47 unrouted)
  Top 0.254: 42,110 42,112 | C4.- 53,109 | 42,108 42,110 | 42,110 RSENS.2
  Top 0.406: C7.- 91.55,81.45 88.7,82.4 85.8,82.4 R8.1 84.9,82.1 v83.6,83.3 | C9.2 94.1,95.1 v95.4,93.8 | TRAFO.5 82.5,86.5 83,87 R4.1
  Top 0.5: C4.- 59,109 60,108 60,98 | D5.A 34,37.4 | FUSE.4 36.4,51.4 36,51 | 46,42 46,47
  Top 1: v75.7,90.2 75.7,92.35 T3.E | 34,37.4 v34,38
  Top 1.5: v55.3,19.9 54.9,21.1 | C8.- 55.3,19.7 55,20
  Bottom 0.406: v75.7,90.2 76,76 MAS1.1 | v95.4,93.8 95.4,92.4 95,92 | 83,83 v83.6,83.3
  Bottom 0.5: 60,102 MINUS.1
  Bottom 1: 46,90 57,101 | 60,99 60,102
  Bottom 1.5: v34,38 34,48 38,52 38,64
  other vias: 49,39 57,64 57,71 46,48 59,34 45,76
  pour Bottom (isolate 2): 96,97 96,73 73,73 73,97
  pour Top (isolate 2, rank 5): 96,97 96,73 73,73 73,97
  pour Bottom (isolate 1, rank 4): 40,80 60,100 99,100 99,22 89,12 89,4 29,4 29,14 44,28 46,30 46,38 40,38
  pour Top (isolate 1, rank 4): 51,94 57,100 100,100 98,23 88,4 26,4 26,10 45.5,30 45.5,47 43,47 42,49 33,49 29,53 29,85 43,85
  pour Bottom (isolate 2, rank 2): 40,113 44,113 44,108 45,107 54,107 54,110 62,110 62,107 71,107 71,110 86,110 87,109 87,101 40,101
  pour Top (isolate 2, rank 2): 32,121 44,121 44,108 45,107 54,107 54,110 62,110 62,107 71,107 71,110 86,110 87,109 87,101 41,101 32,110
  pour Bottom (isolate 1.5): 45,91 47,90 37,80 35,80 33,82 32,81 32,78 39,71 39,64 37,64 35,65 35,72 30,77 30,82 34,86 37,83
N$1
  Top 0.406: VENT.1 29.27,6.97 | 29.3,7.5 30,9.8 Q5.3
  Top 1.5: 29.27,6.97 29.3,7.5
N$2
  Top 0.406: Q5.1 R2.2
N$3
  Top 0.4: R2.1 JP7.17
N$4
  Top 0.5: R18.1 41.84,38.66 2HBRDG.5
N$5
  Top 0.5: D12.A 44.8,69.7 R17.2 43.25,69.75 43,70 36,70 | 35.6,70 36,70 | 1LODRV.3 36.33,70.33 36,70 | 1LODRV.2 36.33,69.67 36,70
  Top 1: R33.1 35.6,70
N$6
  Top 0.406: 81.95,94.25 R3.2
  Top 1: TRAFO.1 81.95,94.25
N$7
  Top 0.406: 91.15,94.3 C9.1
  Top 1: TRAFO.2 91.15,94.3
N$8
  Top 0.406: R11.2 94.2,90.15 R6.2
N$9
  Top 0.5: R22.2 43.9,53.1 43,54 41.69,54 FUSE.5 41,54 40.1,54.2 | FUSE.3 37.6,55.4 40.1,54.2 | R21.1 39.53,54.48 40.1,54.2
N$10
  Top 0.406: R8.2 84.8,80.1 R13.1 D3.A
N$11
  Top 0.5: HBDRVS.5 43.19,88.81 44,88 44,87.59 R17.1
N$12
  Top 0.5: 2HBRDG.7 40.7,35 40.2,34.3 37.2,31.3 37.2,31.2 36.11,30.11 | 36.11,30.11 2HIDRV.2 | 36.11,30.11 2HIDRV.3
  Top 1: R36.1 36.11,30.11
N$13
  Top 0.5: HBDRVS.7 39.5,93.4 37.45,95.45 | 37.45,95.45 1HIDRV.3 1HIDRV.2 | 37,95 | 37.45,95.45 37,95
  Top 1: R34.1 | 37,95 R34.1
N$14
  Top 0.5: R20.2 31.1,60.25 D19.1
N$15  (1 unrouted)
N$16
  Top 0.5: 2LODRV.2 36.33,43.67 36,44 36,44.2 36.33,44.53 2LODRV.3 | R18.2 38.26,43.74 38,44
  Top 0.6: D11.A 38,44 36,44 36,44.2 35.9,43.97
  Top 1: R35.1 36,44
N$17
  Top 0.406: R26.2 R25.2
  Top 0.5: VREG.1 45.2,20 44.4,20.8 43.1,20.8 R26.2
N$18
  Top 0.5: Q10.E 37,64 44.9,64 D20.3 D21.3
N$19  (1 unrouted)
N$20
  Top 0.5: D1.C 27.1,32.7
  Top 1: 27.1,32.7 D5.K
N$21  (1 unrouted)
N$23
  Top 0.5: R27.1 94.2,7.85 R9.2
N$24
  Top 0.5: D6.C 46.6,97.9 D7.K
N$25
  Top 0.5: Q10.B 36.95,62.05 R19.1
N$26
  Top 0.5: R23.2 33,61.9 Q10.C
N$27  (1 unrouted)
N$29
  Top 0.5: R28.1 92,15 91,16 90.4,16 R29.2 R10.2 88,15.6 R12.E
N$30
  Top 0.5: R12.A 90.49,8.46 R9.1 91,8.05 91,10 92,11 R28.2
O_IFB  (via drill 0.51 pad 1.5, 0.6 pad 1.5)
  Top 0.254: 78.3,14 JP7.1
  Top 0.5: R24.2 C17.1 D19.3 | R24.2 33.1,57 34,57 34.36,56.63 FUSE.2 37.9,56.6 40,55.5 40.3,55.3 FUSE.6 44.64,55.37 v47,54 | R24.2 R23.1
  Top 1.5: v78.3,16 78.3,14
  Bottom 0.5: v78.3,16 74.3,20 59,20 55,24 55,43 47,51 v47,54
PUMP+
  Top 0.254: P+2.1 91,73 91.38,73.27
  Top 0.406: P+1.1 94,75 95,76 95,83 94.65,84.35 R11.1 90.4,85.35 TRAFO.3
  Bottom 0.5: C1.+ 96,109 97,108 97,102 98,101 98,74 96,72 P+2.1
  pour Top (isolate 2, rank 2): 95,86 95,73 91,73 91,77 94,77 94,84.6 90,84.6 90,86
  pour Bottom (isolate 2, rank 3): -16,24 -16,8 7,8 7,14 24,14 27,16 27,103 40,103 40,113 44,113 45,112 45,109 50,109 50,112 64,112 64,108 65,107 70,107 70,112 86,112 89,109 89,107 98,107 98,121 16,121 13,111 6,111 6,118 -17,118 -17,102 5,102 5,107 14,107 19,112 29,112 29,108 22,108 20,105 20,21 18,19 6,19 6,24
  pour Top (isolate 2, rank 4): 3,24 3,8 7,8 7,14 24,14 26,16 27,103 39,103 39,113 44,113 45,112 45,109 50,109 50,112 64,112 64,108 65,107 70,107 70,112 86,112 89,109 89,107 99,107 99,121 32,121 32,111 6,111 6,118 1,118 1,102 6,102 6,108 23,108 23,21 18,17 6,17 6,24
RED  (via drill 0.6 pad 1.5)  (3 unrouted)
  Top 0.5: HVL1.2 58.9,31.15 59,31.5
  Route2 0.5: L2.1 L1.2
  other vias: 17,31.5
  pour Bottom (isolate 2, rank 4): 2,48 13,48 13,45 8,45 6,43 6,34 18,34 18,24 11,20 10,20 9,21 2,27
  pour Top (isolate 2): 10,23 11,35 18,35 18,24 19,24 17,22 15,22 14,21 10,21
  pour Top (isolate 2, rank 3): 1,63 13,63 13,60 7,60 7,48 13,48 13,45 8,45 6,43 6,35 12,35 12,21 11,20 10,20 9,21 9,27 1,27
SCR2
  pour Top (isolate 2): 95,53 95,50 81,50 81,53
  pour Bottom (isolate 2): 95,53 95,50 81,50 81,53
SNUB1
  pour Top (isolate 2, rank 2): 79,53 79,41 72,41 72,53
  pour Bottom (isolate 2, rank 2): 79,53 79,41 72,41 72,53
SNUB2
  pour Top (isolate 2, rank 2): 79,37 79,25 72,25 72,37
  pour Bottom (isolate 2, rank 2): 79,37 79,25 72,25 72,37
SOURCE
  pour Top (isolate 2): 95,37 95,34 81,34 81,37
  pour Bottom (isolate 2): 95,37 95,34 81,34 81,37
TFB  (1 unrouted)
  Top 0.4: C2.1 40,13.22 JP7.16 40,12.78 40,10 36.1,6.1 NTC.1
  Top 1: JP1.16 40.22,-9.78 40,-10 39,-10 | 39,-10 37,-10 37,-7.68 JP1.17 | R37.2 39,-10
V12  (via drill 0.6, 0.6 pad 1.27, 0.6 pad 1.5)
  Top 0.254: V12_2.1 82,72 82,73 82.17,73
  Top 0.406: C7.+ 88.45,77.45 87,76 84,76 V12_1.1 | V12_1.1 R13.2 | D9.K 80,78 V12_1.1 | JP7.12 50.2,13.18 | VENT.2 26.73,6.27
  Top 0.5: 31,67 30.4,67.6 30.17,67.6 1LODRV.8 | 34.75,67.25 34.5,67 | 50.3,12.92 JP7.12 | HBDRVS.1 35.14,82.46 D10.A C14.1 34.55,81 v33,81 | 2LODRV.8 29.67,41.33 30,41 | 2LODRV.1 36.33,41.67 37,41 | 1LODRV.1 36.33,67.33 36,67 | R21.2 41.55,51.45 v42,52
  Top 0.6: D8.A 48.4,31.5 2HBRDG.1 | v43,41 C16.1 | 41.69,58.7 FUSE.8
  Top 1: v43,41 41,41 | 41,41 37,41 30,41 29.69,41 | v42,59.7 41.69,58.7 | v72,67 83,67 V12_2.1 | 34.5,67 31,67 | 34.75,67.25 35,67 36,67 v42,67 41,68 C15.1 | v50.3,10.5 50.3,12.92 | C16.1 41,41 | 50.34,13.04 IC3.3 50.3,16.14 50.3,16.8 50,17.1 50,18 | VREG.3 49.8,18.2 50,18 | C8.+ 50.1,17.9 50,18
  Top 1.016: 52.75,30.6 C13.1
  Top 1.5: 52.75,30.6 v50.8,30.6 50.3,31.1 D8.A | JP7.12 50.34,13.04 | 26.73,6.27 v26.7,8.7
  Bottom 0.406: v26.7,8.7 27,9 | v50.8,30.6 50.4,31
  Bottom 0.5: 50,17 50.1,17 50.3,16.8 | 50,30.5 49.68,30.6 50,30.6 v50.8,30.6 | 42,49 v42,52
  Bottom 1: 27,9 30,13 32,16 48.3,32.3
  Bottom 1.5: v42,67 v42,59.7 42,49 42,42 v43,41 42,40 42,38.6 48.3,32.3 50,30.6 | v33,81 42,72 v42,67 | v42,67 v72,67 | 50.3,16.8 v50.3,10.5 | 50,30.5 50,17
  pour Top (isolate 2): 89,79 89,73 80,73 80,78 87,78
VB  (3 unrouted)
VB1
  Top 0.406: D10.K 35,89 38.27,89 HBDRVS.8
  Top 0.5: 1HIDRV.1 34.3,94.3 33,93 32,93 29,96 29,97.71 1HIDRV.8 | C21.1 36.8,91.8 36,91
  pour Top (isolate 1.5, rank 2): 29,99 39,90 38,88 34,88 26,96
VB2
  Top 0.5: 39.18,29 40,29 41,30 | 41,30 42,31 41.99,31.01 2HBRDG.8 | D8.K 42.4,31 41,30 | 2HIDRV.1 37.45,28.55 38,28 | 2HIDRV.8 32.95,24.05 34,23
  pour Top (isolate 1.5): 33,23 34,22 43,31 43,33 42,33 33,24
VDD  (2 unrouted)
  Top 0.4: NTC.2 32.83,8.83 34,10 34,14.4 38,17 45.16,17 IC3.1
  Top 0.5: IC3.1 45.26,17.56 45.5,17.8 46.4,17.8 46.7,18.1 | VREG.4 47.5,23.5 47.9,23.1
  Top 1: R26.1 47.9,23.1 48,23 48,21.6 47.6,21.2 47.6,19 46.7,18.1
  Top 1.5: JP7.14 45.3,16.06 IC3.1
  pour Top (isolate 0.8): 45,25 53,25 53,24 51,20 49,20 49,19 46,15 43,15 43,23
VFB  (via drill 0.6 pad 1)  (2 unrouted)
  Top 0.4: C10.1 44.2,5.2 44,5
  Top 0.5: R12.S 86,11 82,5 44,5 | JP7.15 42.76,9.84 C10.1
  Top 1: v56.7,-12.3 54.19,-13.19 | v43,-10 43,-7.24 JP1.15
  Bottom 1: v43,-10 44.7,-11.7 53.4,-11.7 v56.7,-12.3
VS  (1 unrouted)
VS3
  Top 0.5: D1.A 25.3,28.51 ROUT6.1 | 36,33.19 36,34 37.4,34.4 38.1,35 39.06,36 39.33,36.27 2HBRDG.6 | 2HIDRV.5 30.05,26.95 29,28 | 2HIDRV.4 34.55,31.45 34,32
  Top 1: 29,28 25,28 25,27.1 ROUT6.1
  pour Top (isolate 1.5): 24,32 26,32 29,29 30,29 36,35 42,35 42,34 38,34 31,27 28,26 24,29
VS4
  Top 0.5: HBDRVS.6 40.8,88.84 40.8,90.3 41.8,91.3 41.8,91.4 41.4,91.8 C21.2 | 1HIDRV.5 32.99,101.99 34,103 34,102.1 C11.2 38,98.1 38,98 37.7,97.7 1HIDRV.4
  pour Top (isolate 1.5): 26,107 30,107 39,98 44,98 44,93.5 41,90.5 40,95 34,101 33,101 29,105 26,105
